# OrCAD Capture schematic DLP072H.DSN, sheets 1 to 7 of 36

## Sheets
1 PAGE35 - REVISION HISTORY
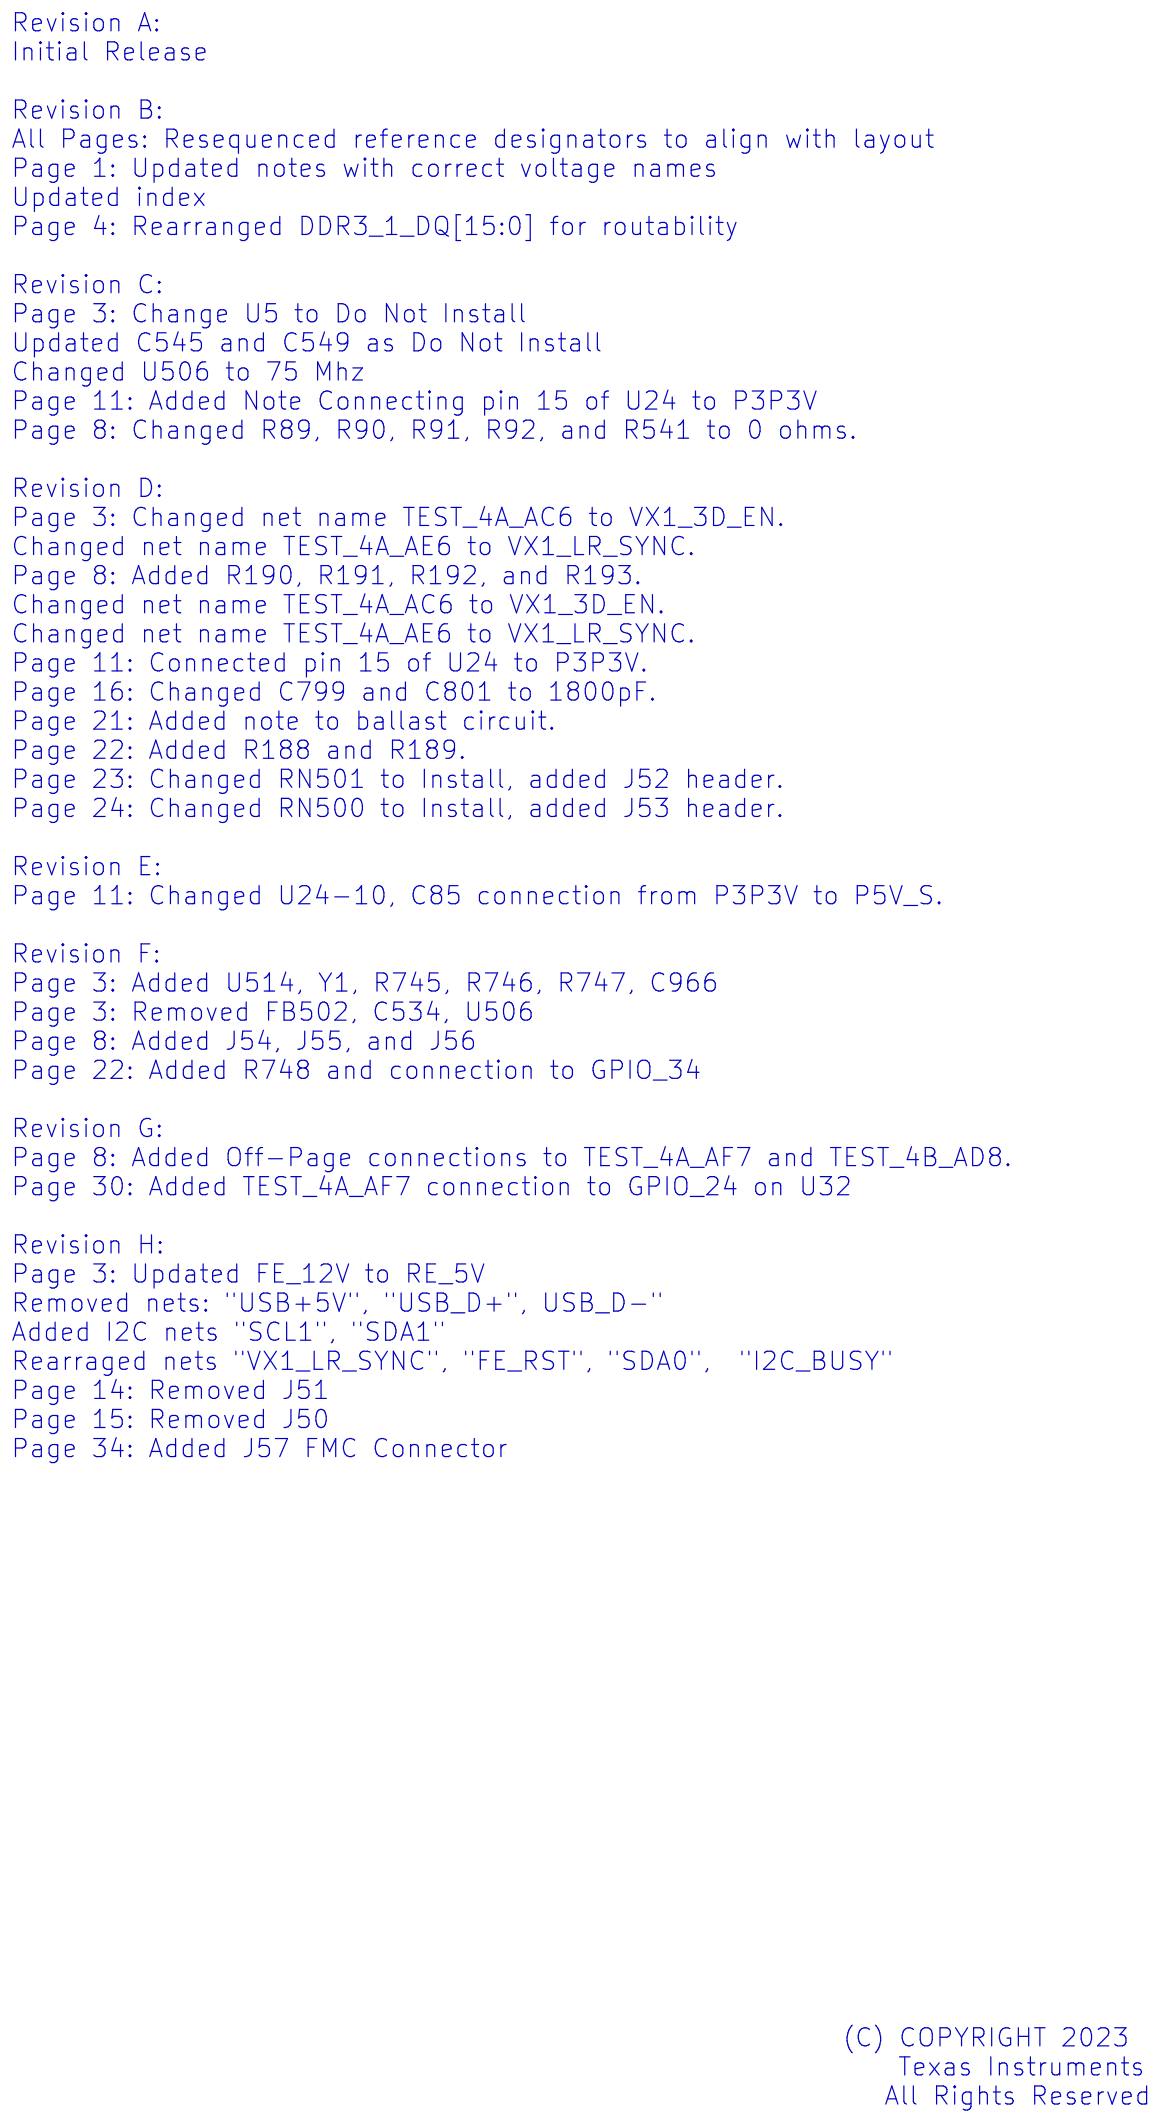
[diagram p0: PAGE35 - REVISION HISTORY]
2 PAGE34 - OUTPUT FMC CONNECTOR: size D
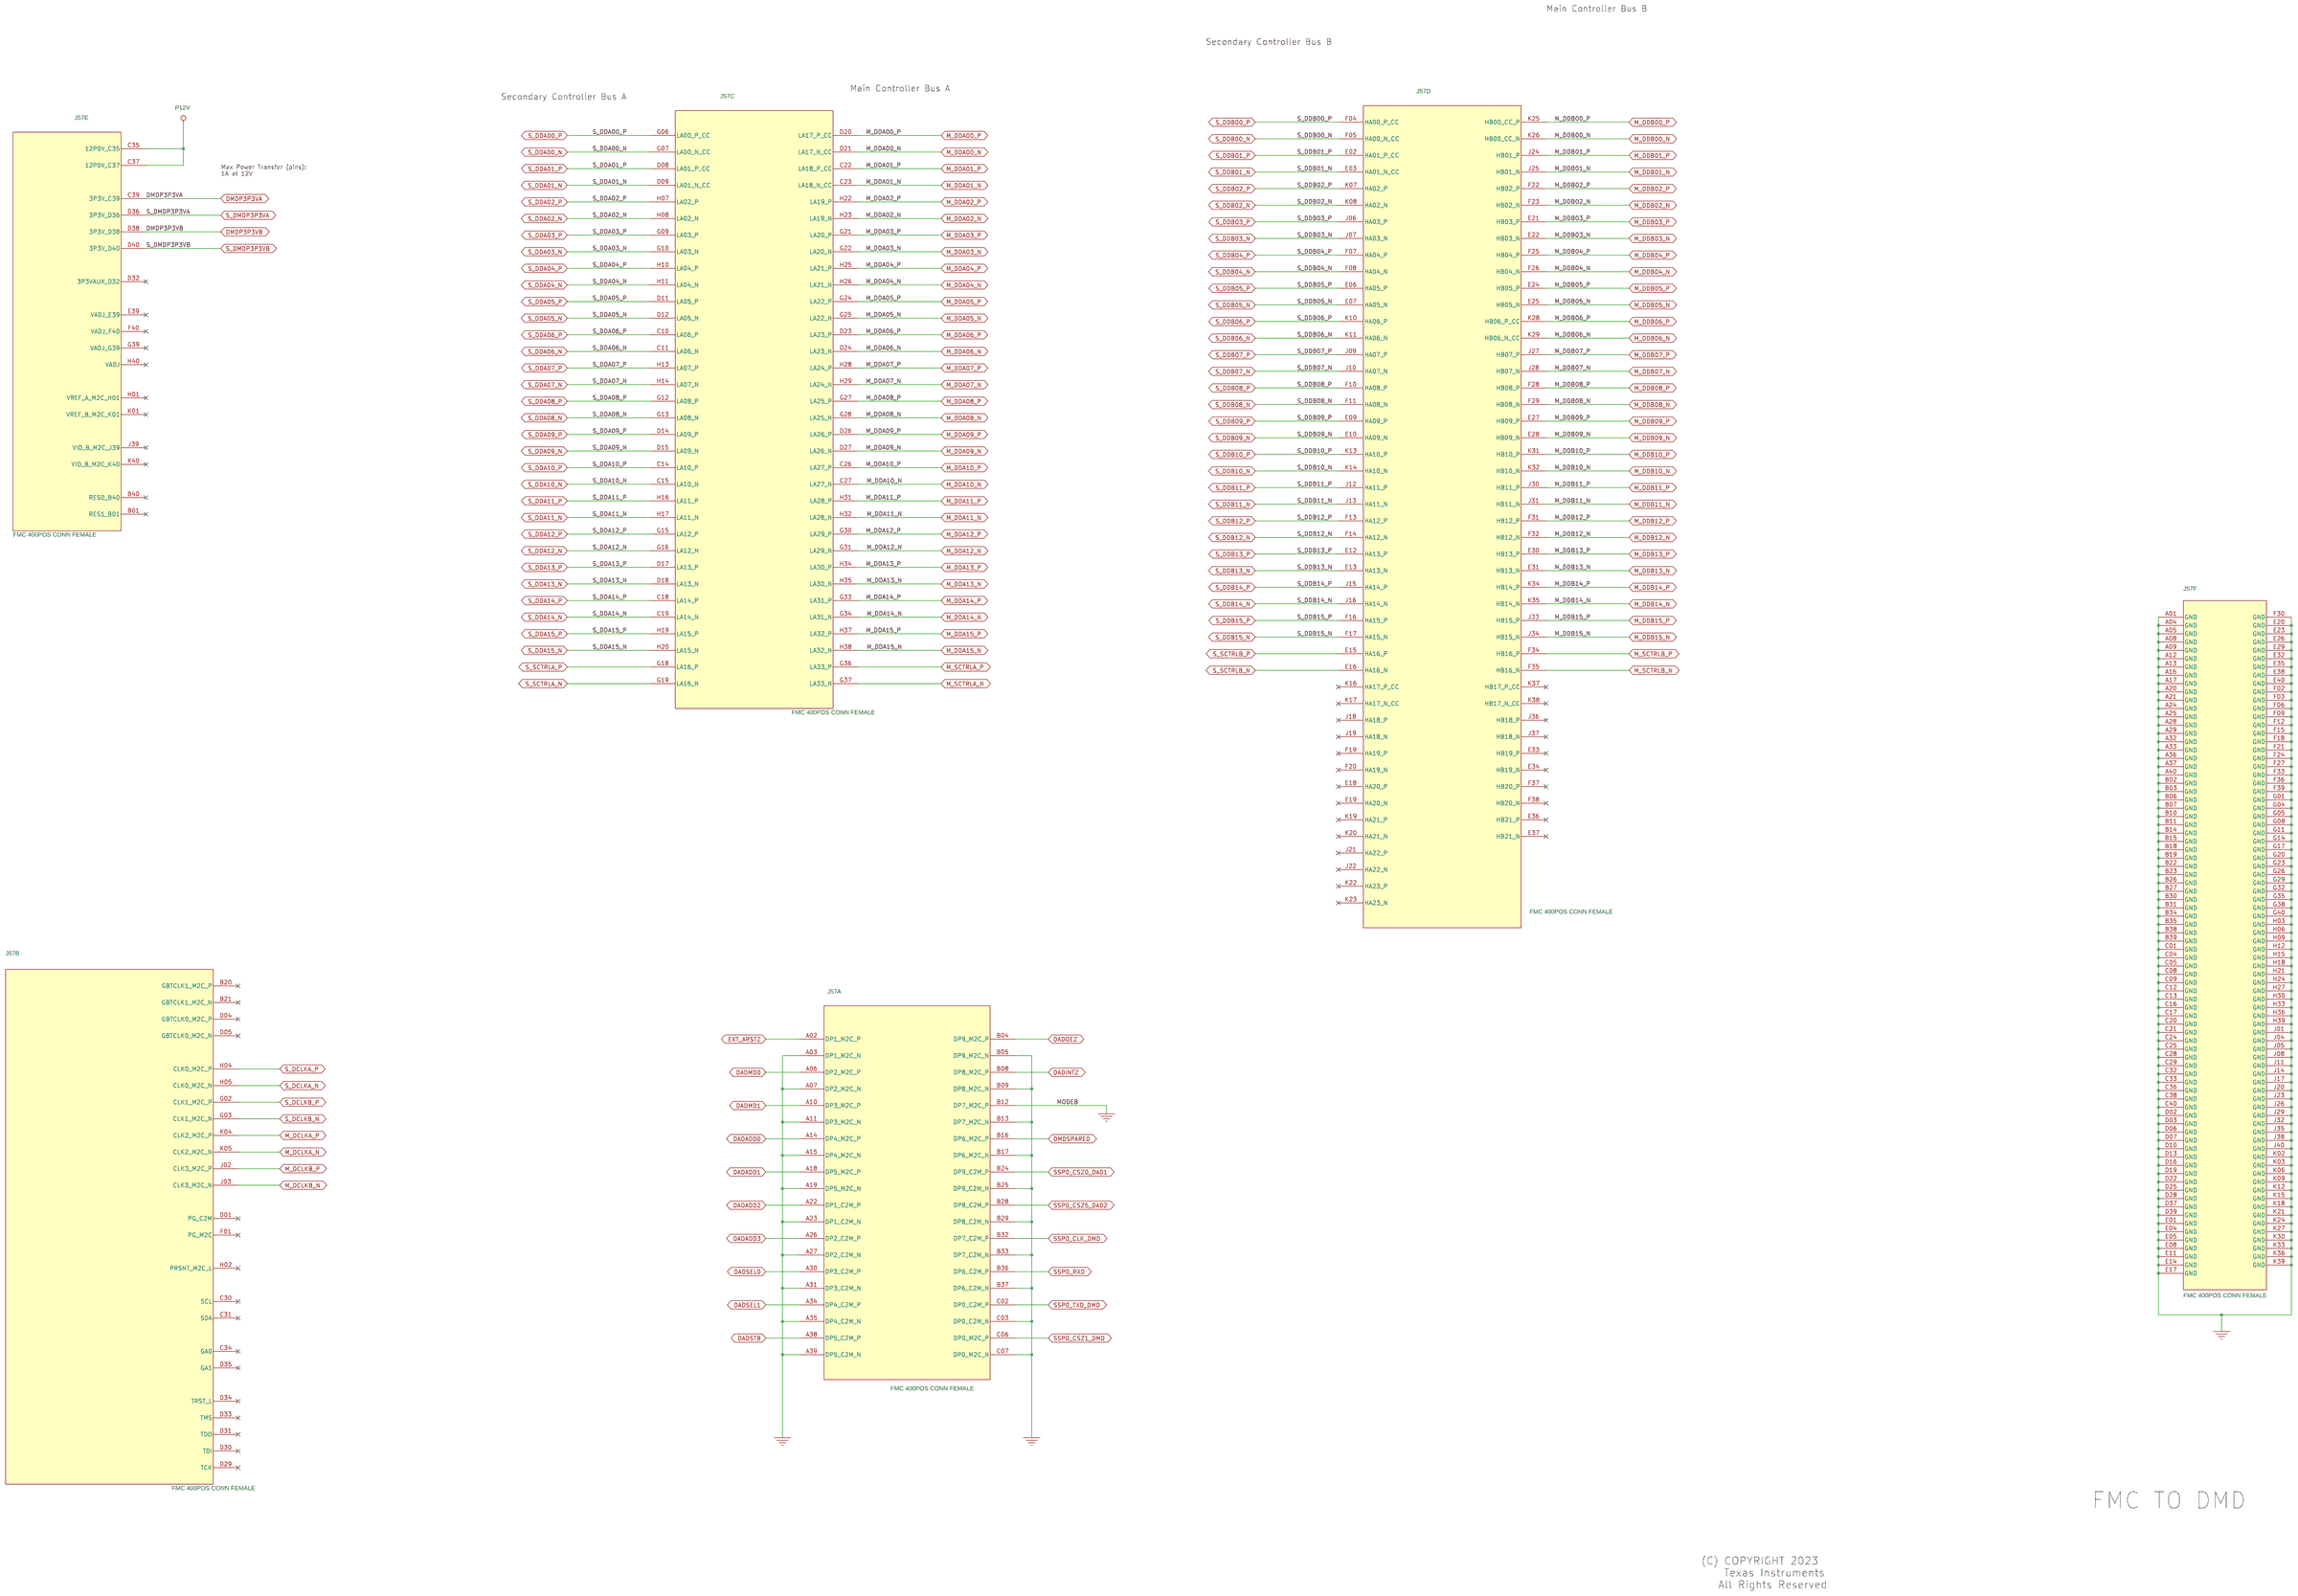
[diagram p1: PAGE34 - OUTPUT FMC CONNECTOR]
3 PAGE01 - TITLE
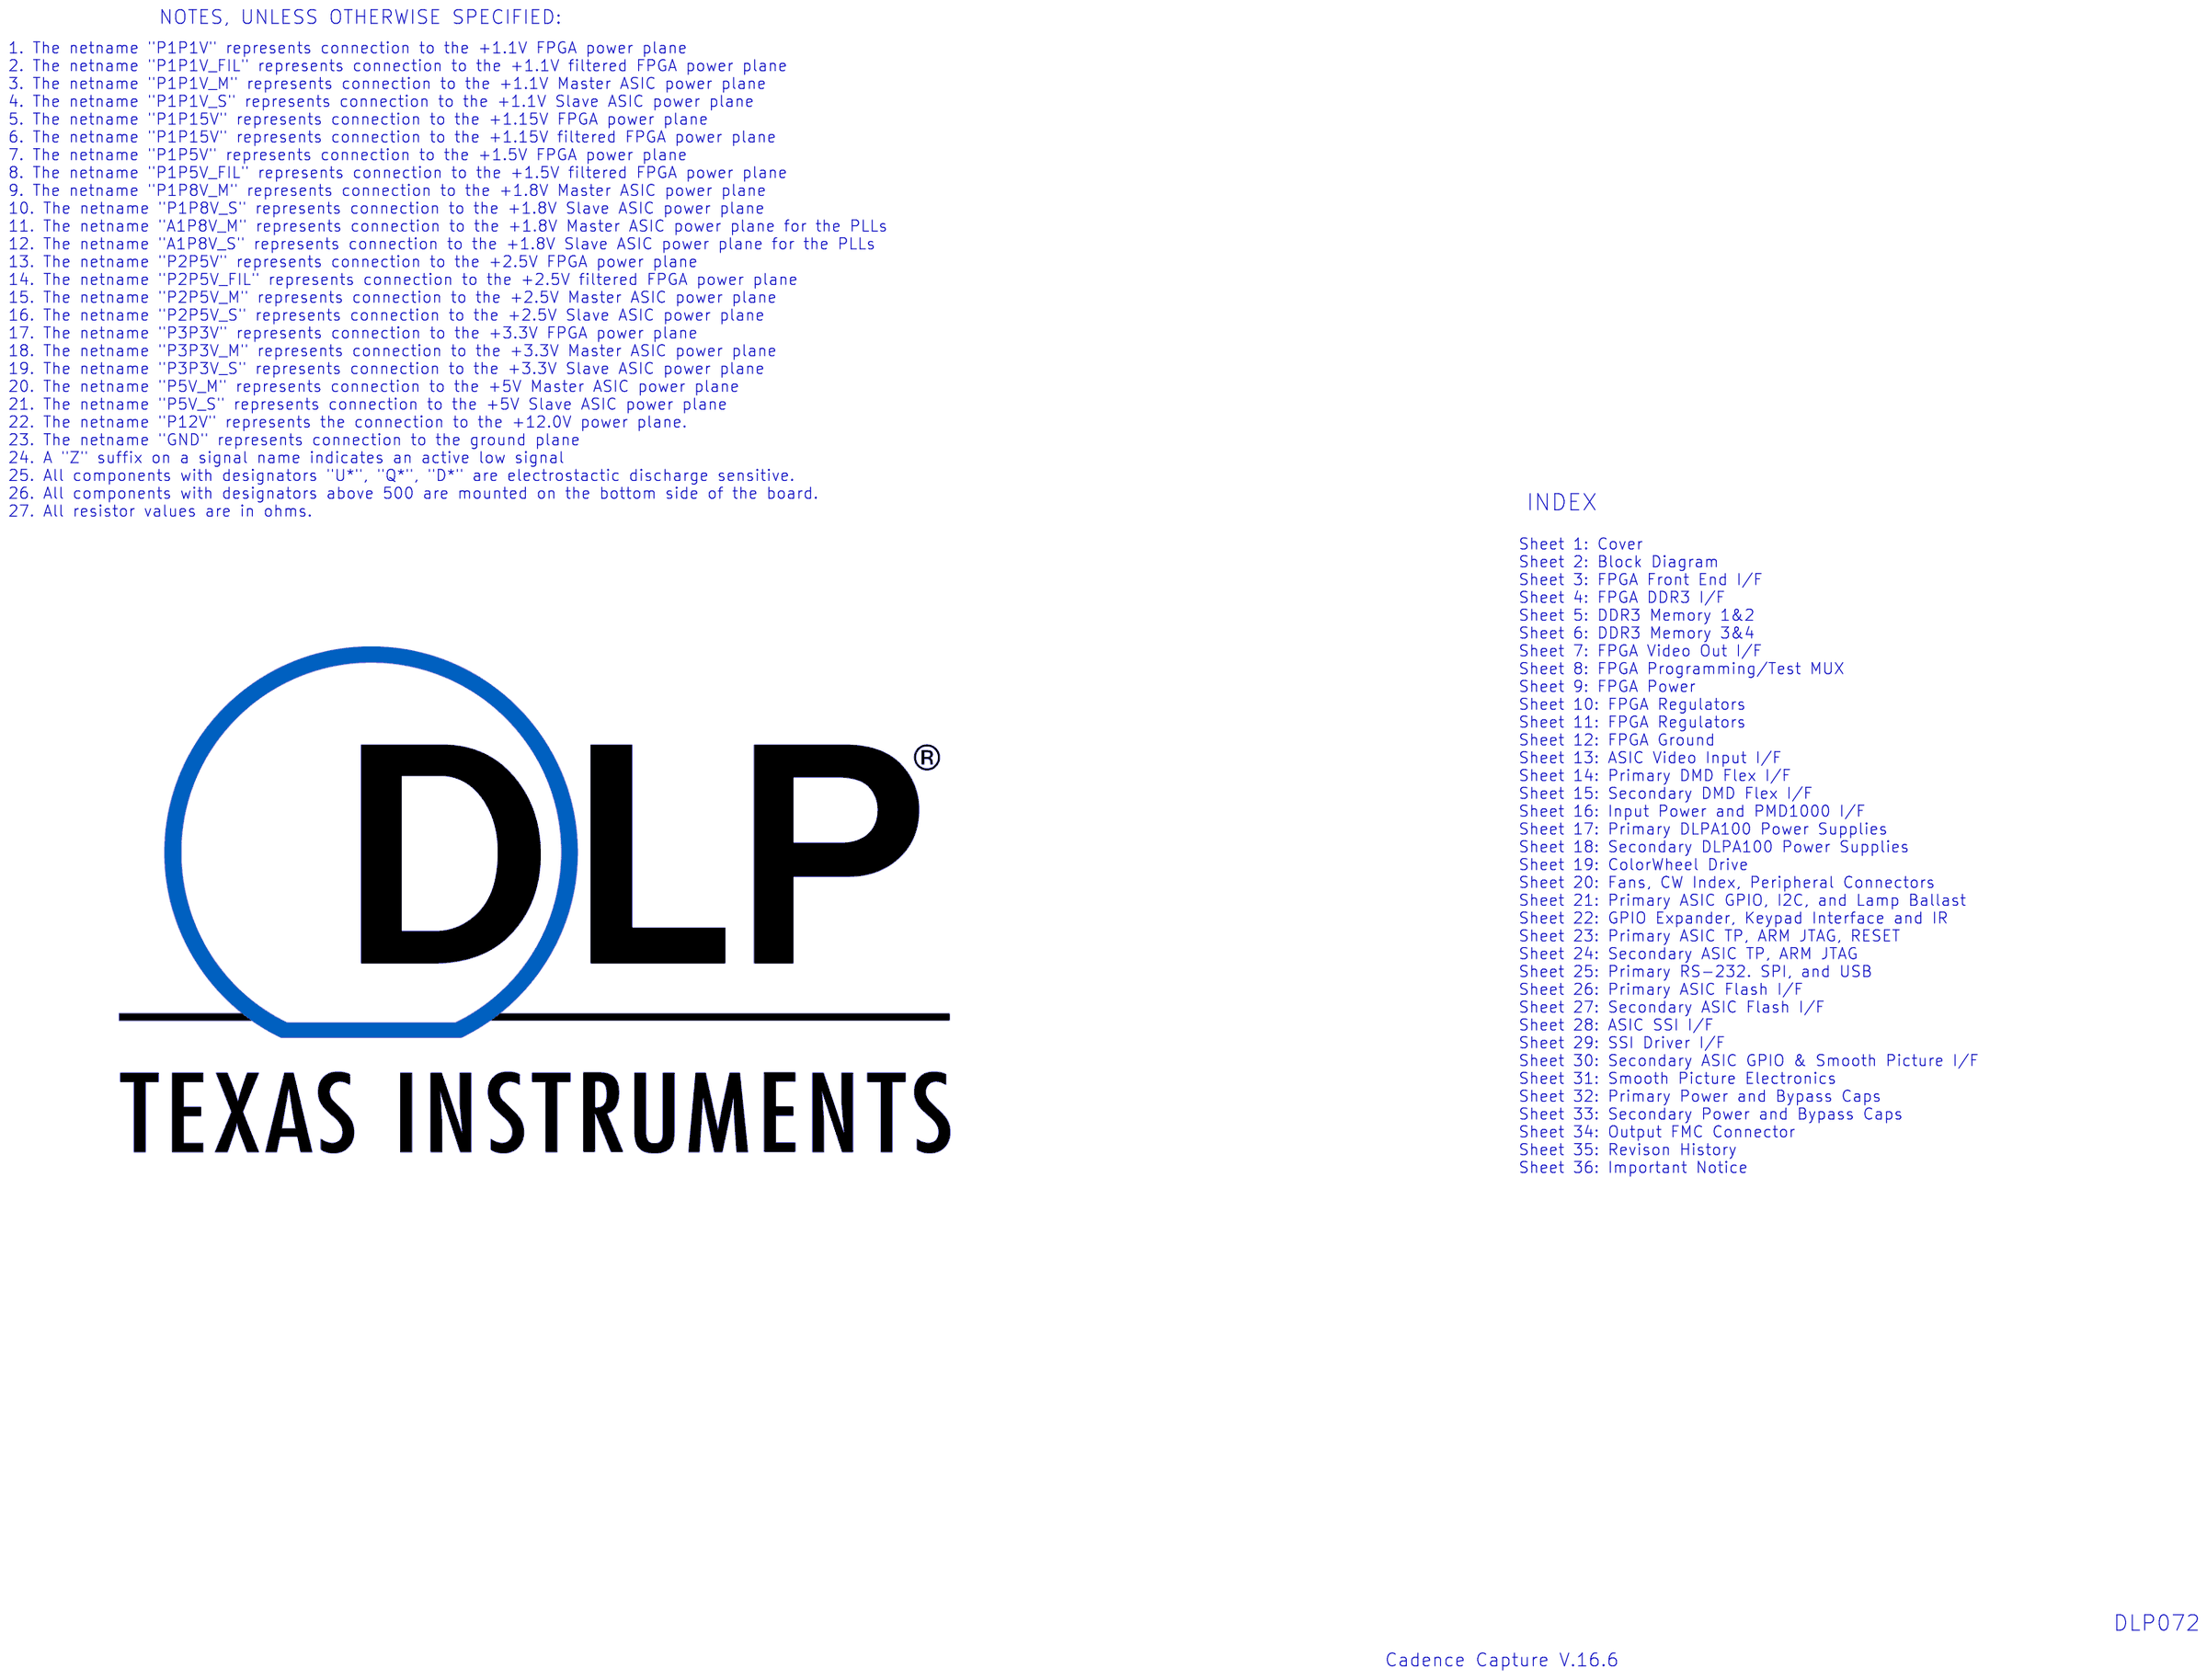
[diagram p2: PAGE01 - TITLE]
4 PAGE02 - BLOCK DIAGRAM
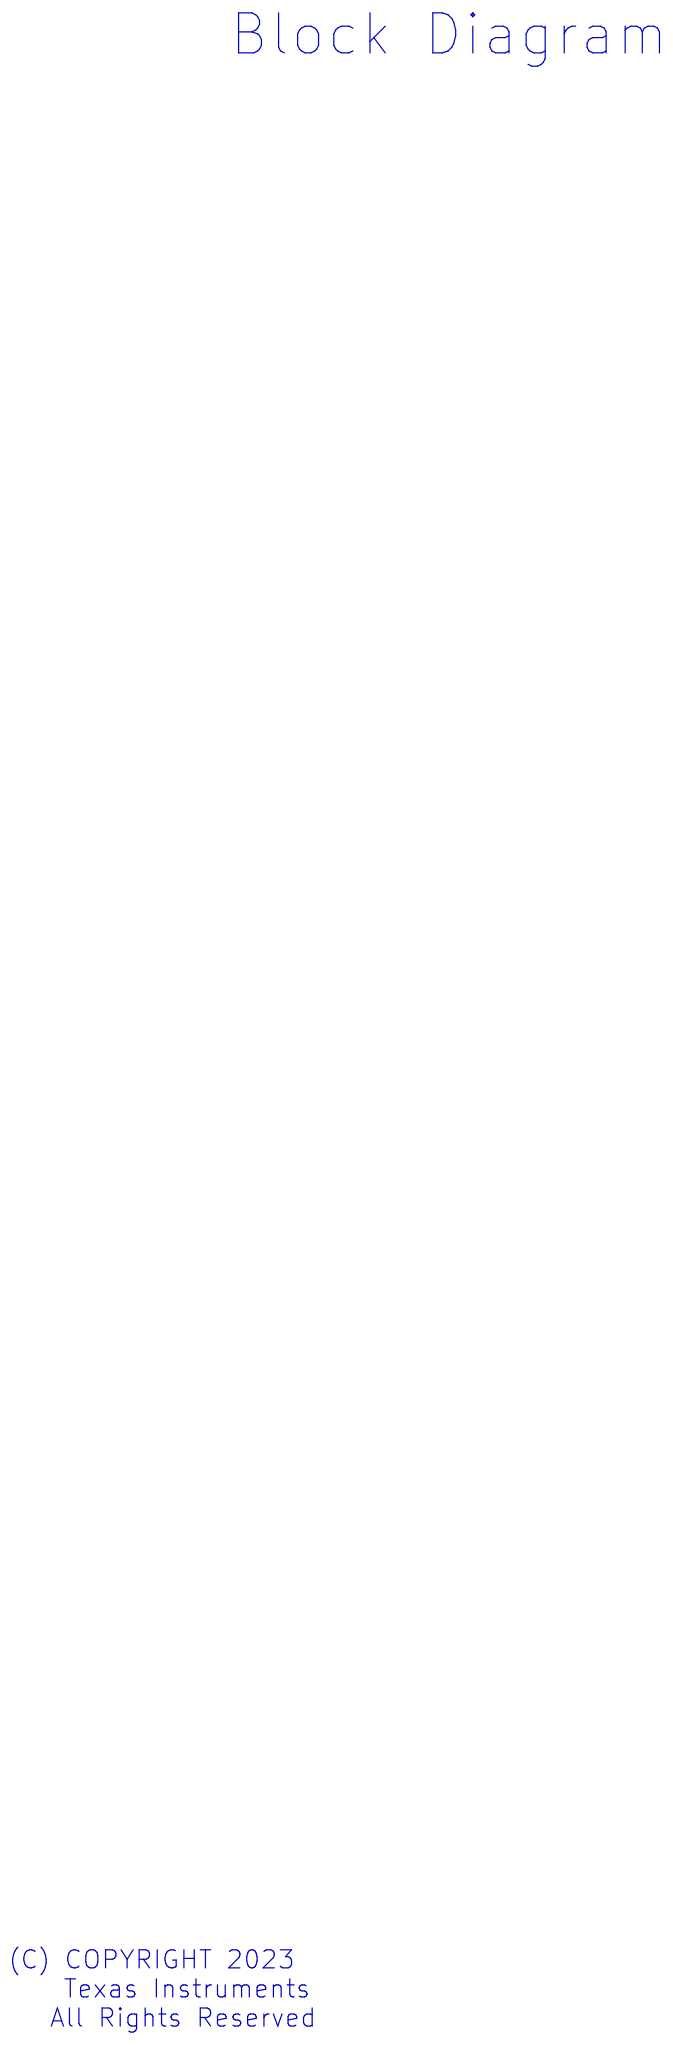
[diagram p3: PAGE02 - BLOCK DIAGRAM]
5 PAGE05 - DDR3 Memory: size A3
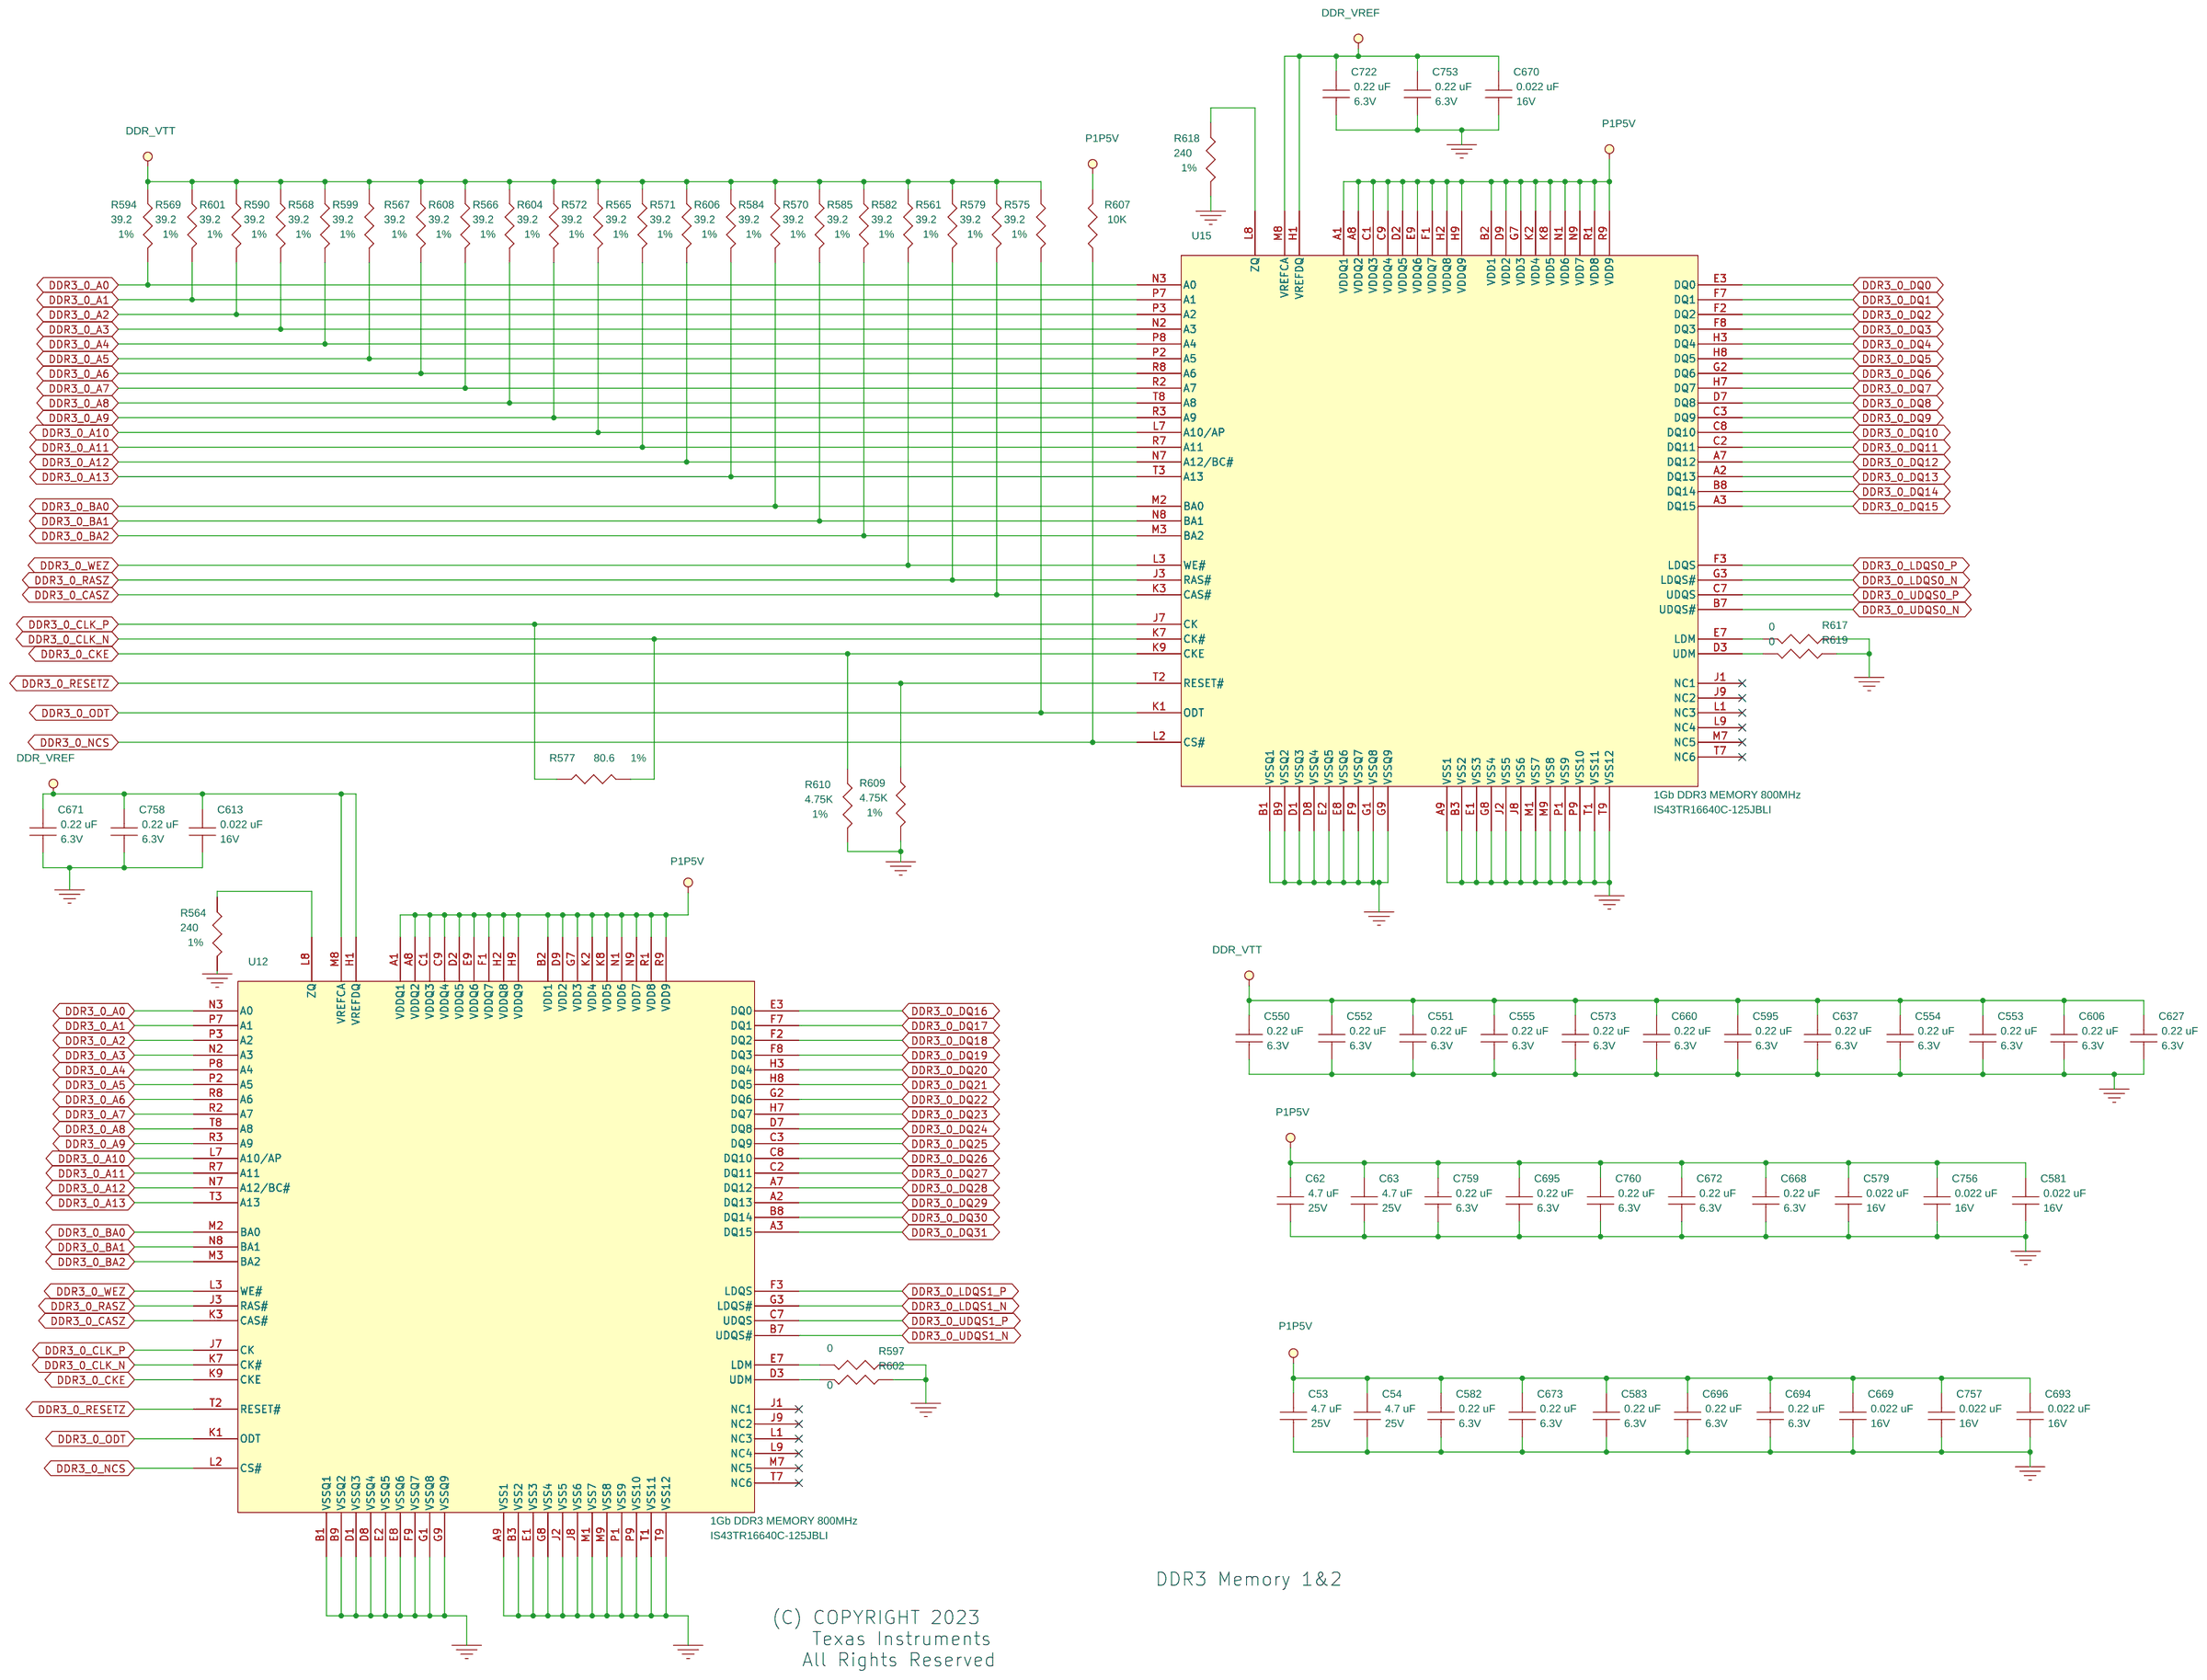
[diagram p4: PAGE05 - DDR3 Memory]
6 PAGE06 - DDR3 Memory: size A3
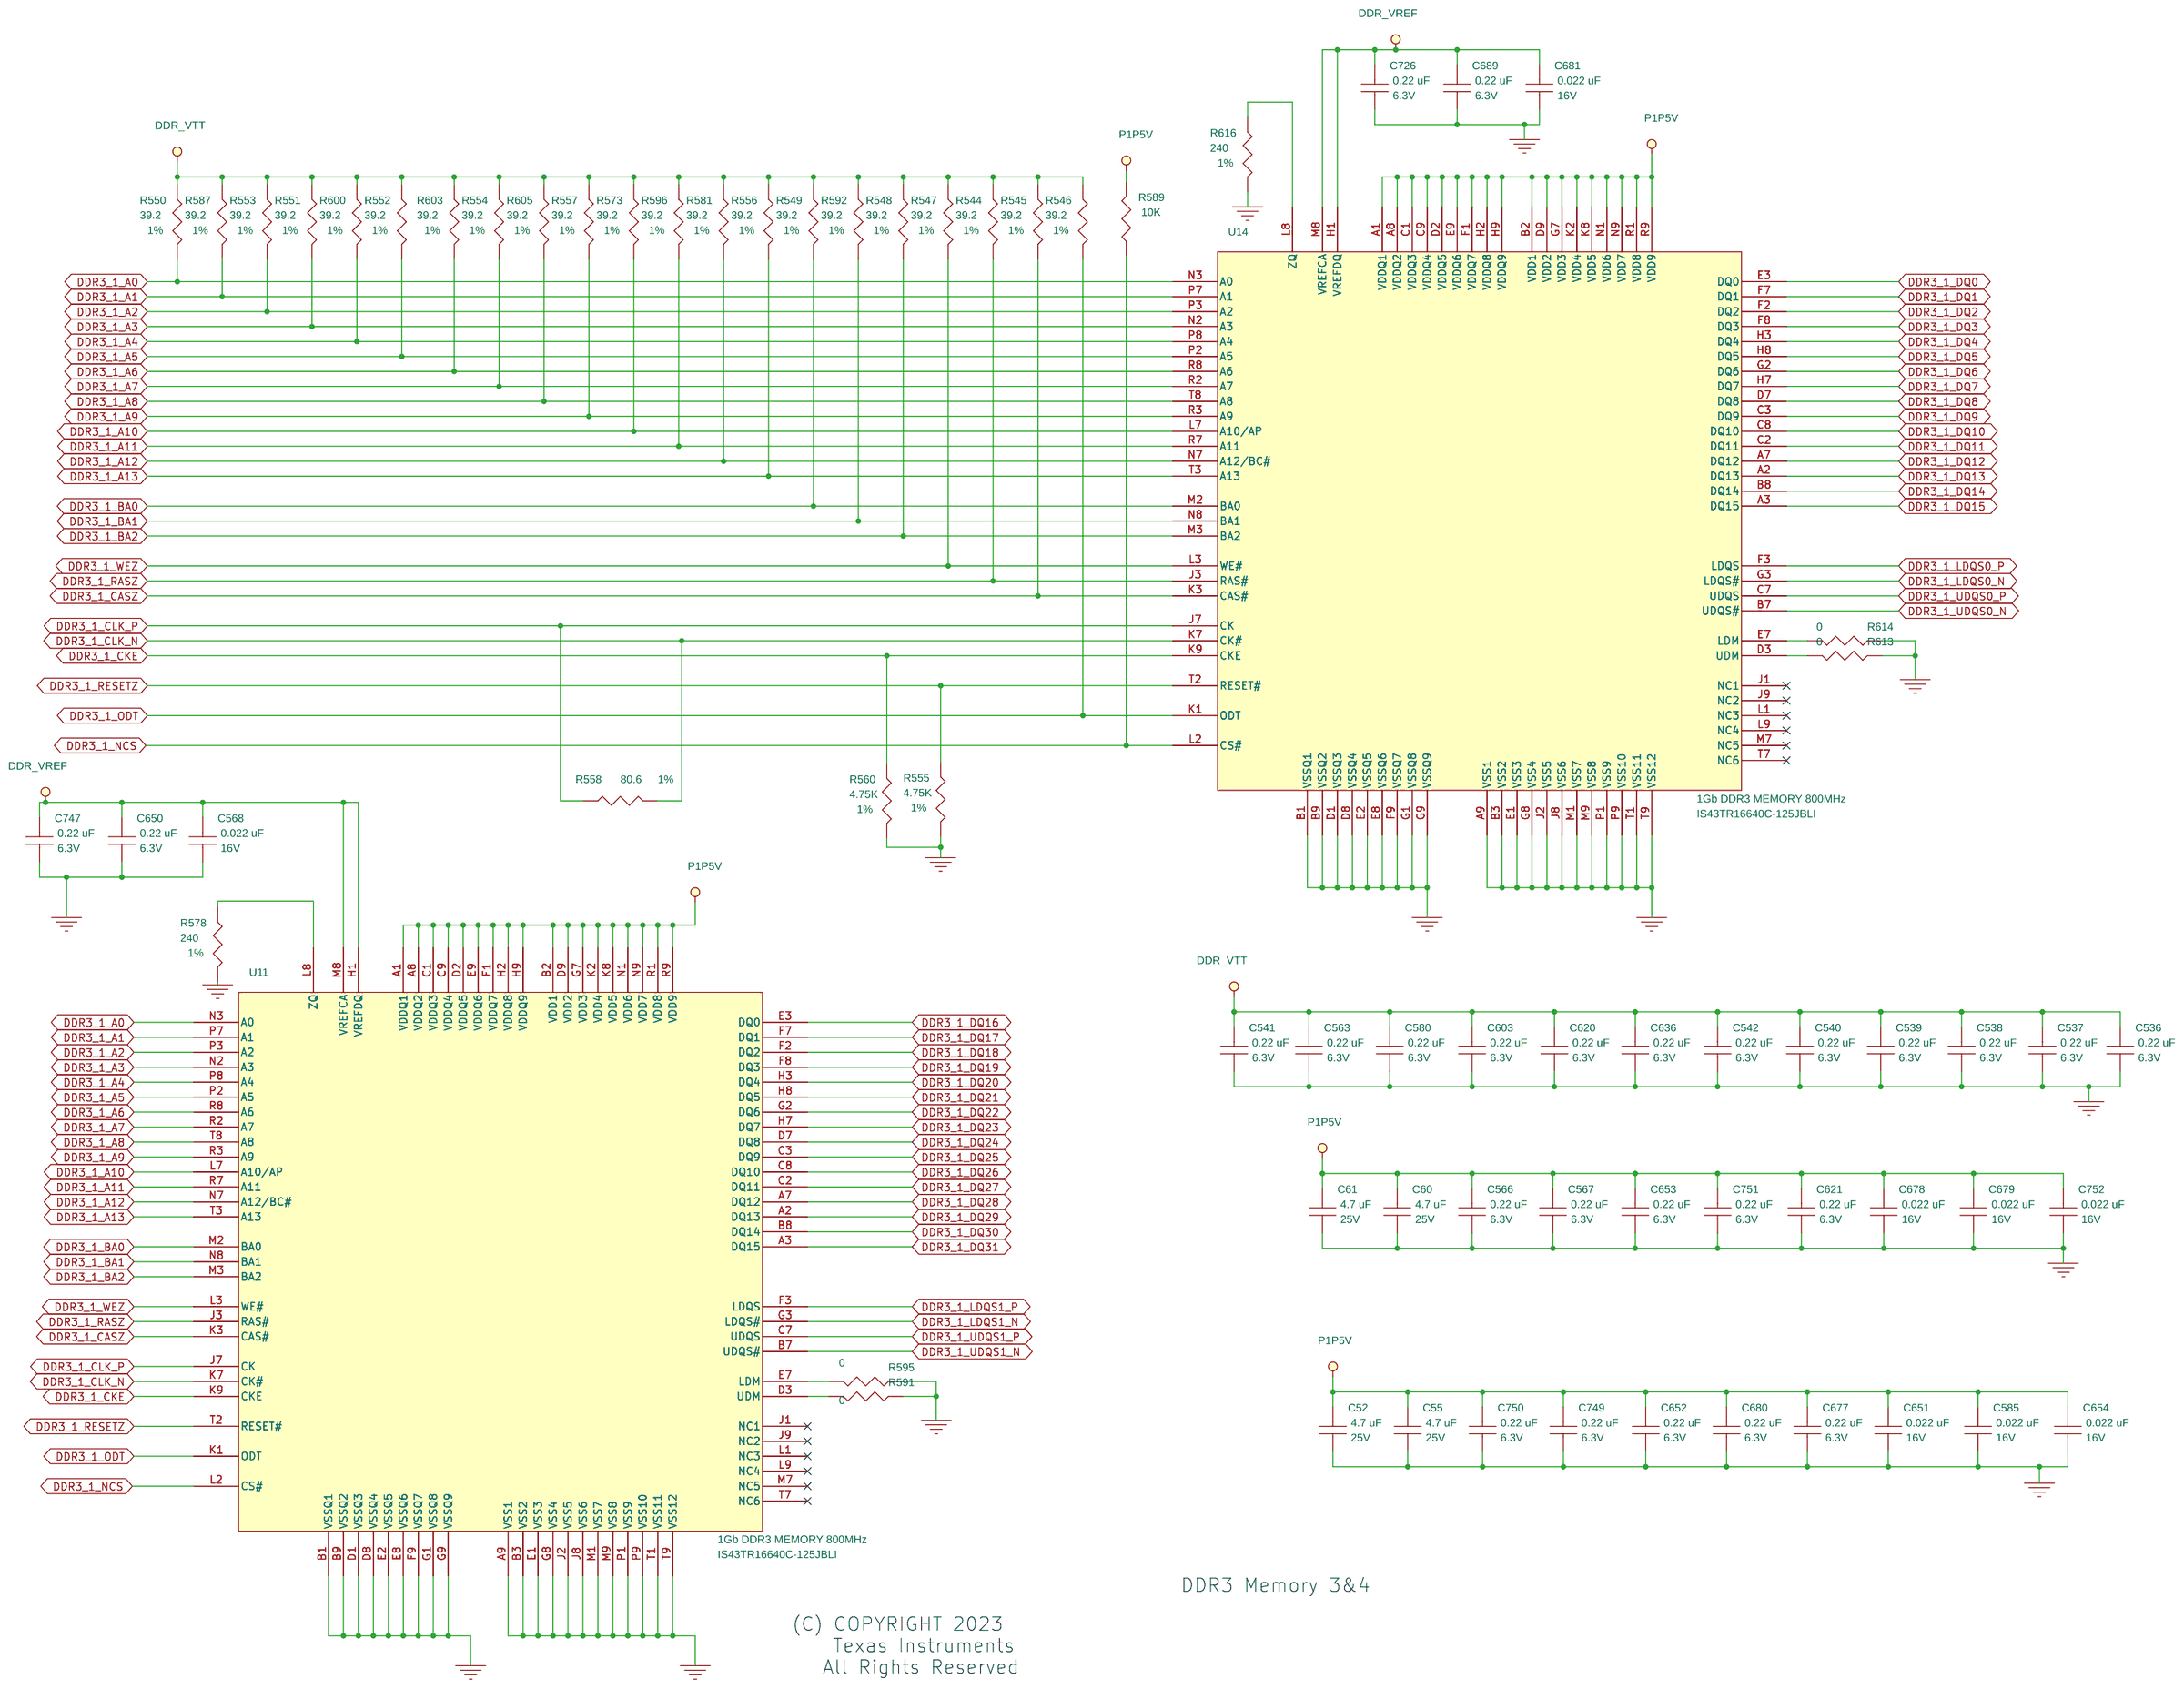
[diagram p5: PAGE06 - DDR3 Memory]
7 PAGE09 - FPGA POWER: size A3
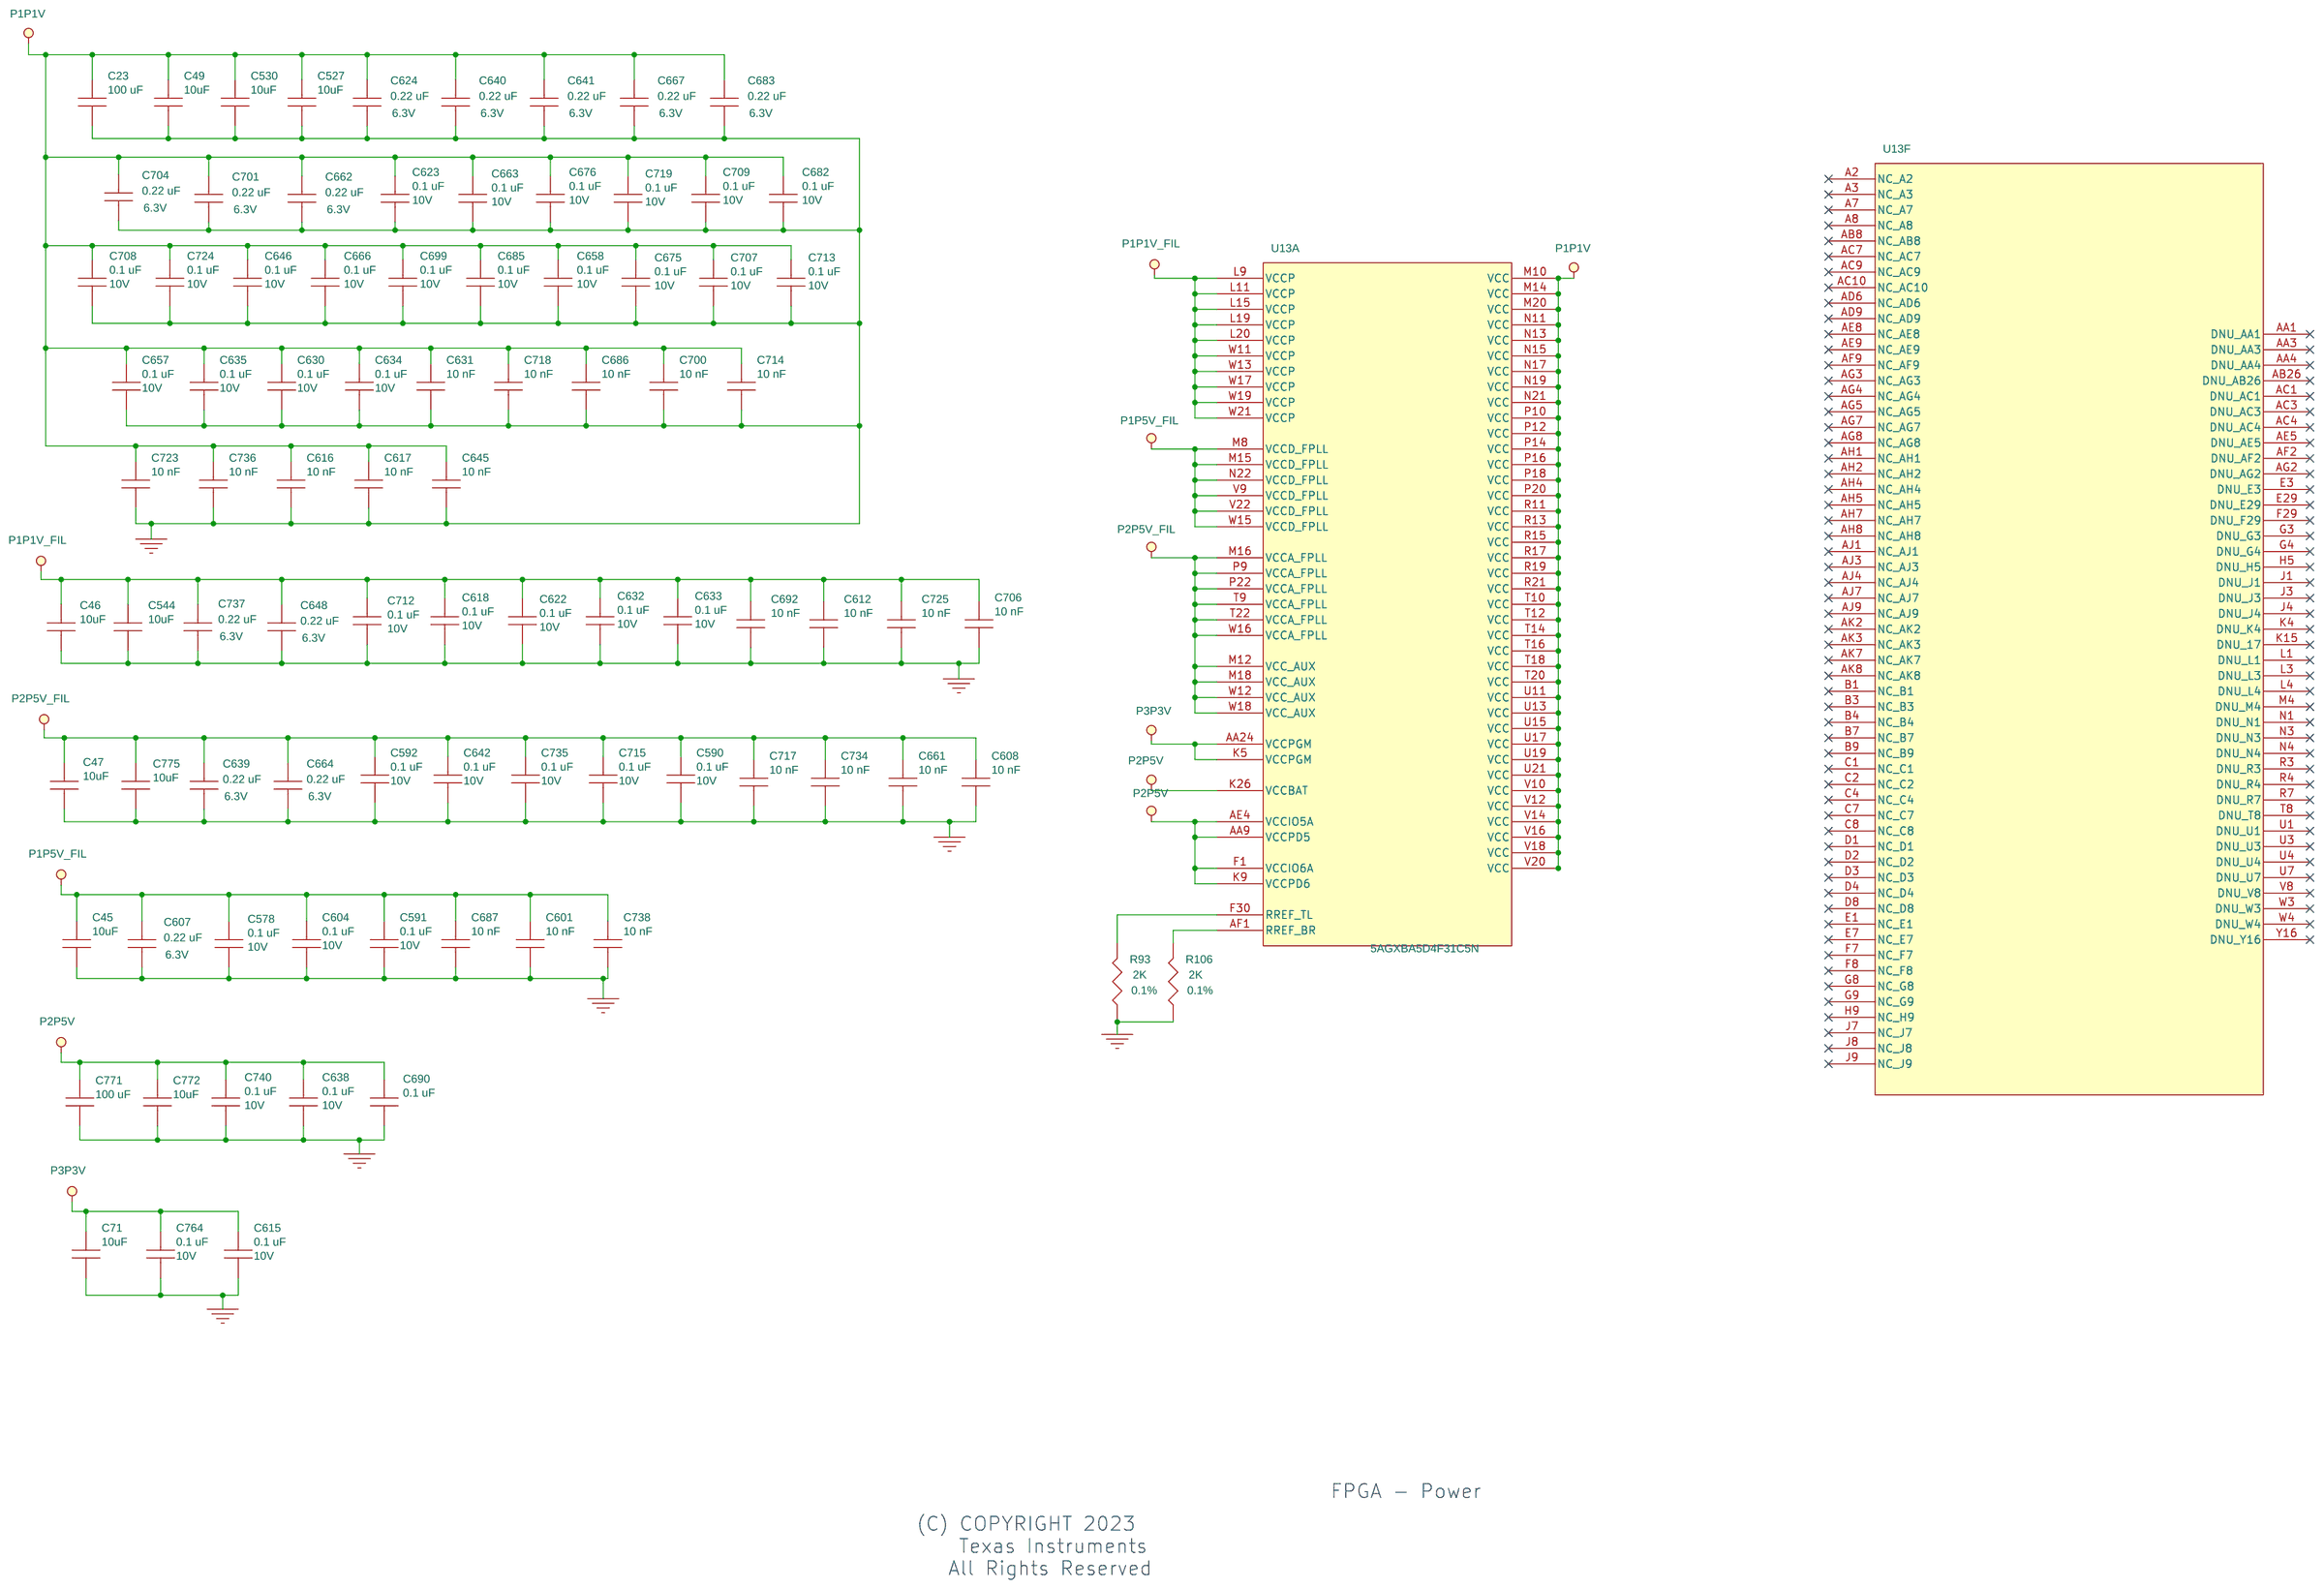
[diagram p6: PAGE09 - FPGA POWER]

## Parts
sheet PAGE05 - DDR3 Memory
C53  4.7 uF  [CAP_0805]
C54  4.7 uF  [CAP_0805]
C62  4.7 uF  [CAP_0805]
C63  4.7 uF  [CAP_0805]
C550  0.22 uF  [CAP_0402]
C551  0.22 uF  [CAP_0402]
C552  0.22 uF  [CAP_0402]
C553  0.22 uF  [CAP_0402]
C554  0.22 uF  [CAP_0402]
C555  0.22 uF  [CAP_0402]
C573  0.22 uF  [CAP_0402]
C579  0.022 uF  [CAP_0402]
C581  0.022 uF  [CAP_0402]
C582  0.22 uF  [CAP_0402]
C583  0.22 uF  [CAP_0402]
C595  0.22 uF  [CAP_0402]
C606  0.22 uF  [CAP_0402]
C613  0.022 uF  [CAP_0402]
C627  0.22 uF  [CAP_0402]
C637  0.22 uF  [CAP_0402]
C660  0.22 uF  [CAP_0402]
C668  0.22 uF  [CAP_0402]
C669  0.022 uF  [CAP_0402]
C670  0.022 uF  [CAP_0402]
C671  0.22 uF  [CAP_0402]
C672  0.22 uF  [CAP_0402]
C673  0.22 uF  [CAP_0402]
C693  0.022 uF  [CAP_0402]
C694  0.22 uF  [CAP_0402]
C695  0.22 uF  [CAP_0402]
C696  0.22 uF  [CAP_0402]
C722  0.22 uF  [CAP_0402]
C753  0.22 uF  [CAP_0402]
C756  0.022 uF  [CAP_0402]
C757  0.022 uF  [CAP_0402]
C758  0.22 uF  [CAP_0402]
C759  0.22 uF  [CAP_0402]
C760  0.22 uF  [CAP_0402]
R561  39.2  [RES_0402]
R564  240  [RES_0402]
R565  39.2  [RES_0402]
R566  39.2  [RES_0402]
R567  39.2  [RES_0402]
R568  39.2  [RES_0402]
R569  39.2  [RES_0402]
R570  39.2  [RES_0402]
R571  39.2  [RES_0402]
R572  39.2  [RES_0402]
R575  39.2  [RES_0402]
R577  80.6  [RES_0402]
R579  39.2  [RES_0402]
R582  39.2  [RES_0402]
R584  39.2  [RES_0402]
R585  39.2  [RES_0402]
R590  39.2  [RES_0402]
R594  39.2  [RES_0402]
R597  0  [RES_0402]
R599  39.2  [RES_0402]
R601  39.2  [RES_0402]
R602  0  [RES_0402]
R604  39.2  [RES_0402]
R606  39.2  [RES_0402]
R607  10K  [RES_0402]
R608  39.2  [RES_0402]
R609  4.75K  [RES_0402]
R610  4.75K  [RES_0402]
R617  0  [RES_0402]
R618  240  [RES_0402]
R619  0  [RES_0402]
U12  1Gb DDR3 MEMORY 800MHz  [BGA96-JT_MICRON]
U15  1Gb DDR3 MEMORY 800MHz  [BGA96-JT_MICRON]
sheet PAGE06 - DDR3 Memory
C52  4.7 uF  [CAP_0805]
C55  4.7 uF  [CAP_0805]
C60  4.7 uF  [CAP_0805]
C61  4.7 uF  [CAP_0805]
C536  0.22 uF  [CAP_0402]
C537  0.22 uF  [CAP_0402]
C538  0.22 uF  [CAP_0402]
C539  0.22 uF  [CAP_0402]
C540  0.22 uF  [CAP_0402]
C541  0.22 uF  [CAP_0402]
C542  0.22 uF  [CAP_0402]
C563  0.22 uF  [CAP_0402]
C566  0.22 uF  [CAP_0402]
C567  0.22 uF  [CAP_0402]
C568  0.022 uF  [CAP_0402]
C580  0.22 uF  [CAP_0402]
C585  0.022 uF  [CAP_0402]
C603  0.22 uF  [CAP_0402]
C620  0.22 uF  [CAP_0402]
C621  0.22 uF  [CAP_0402]
C636  0.22 uF  [CAP_0402]
C650  0.22 uF  [CAP_0402]
C651  0.022 uF  [CAP_0402]
C652  0.22 uF  [CAP_0402]
C653  0.22 uF  [CAP_0402]
C654  0.022 uF  [CAP_0402]
C677  0.22 uF  [CAP_0402]
C678  0.022 uF  [CAP_0402]
C679  0.022 uF  [CAP_0402]
C680  0.22 uF  [CAP_0402]
C681  0.022 uF  [CAP_0402]
C689  0.22 uF  [CAP_0402]
C726  0.22 uF  [CAP_0402]
C747  0.22 uF  [CAP_0402]
C749  0.22 uF  [CAP_0402]
C750  0.22 uF  [CAP_0402]
C751  0.22 uF  [CAP_0402]
C752  0.022 uF  [CAP_0402]
R544  39.2  [RES_0402]
R545  39.2  [RES_0402]
R546  39.2  [RES_0402]
R547  39.2  [RES_0402]
R548  39.2  [RES_0402]
R549  39.2  [RES_0402]
R550  39.2  [RES_0402]
R551  39.2  [RES_0402]
R552  39.2  [RES_0402]
R553  39.2  [RES_0402]
R554  39.2  [RES_0402]
R555  4.75K  [RES_0402]
R556  39.2  [RES_0402]
R557  39.2  [RES_0402]
R558  80.6  [RES_0402]
R560  4.75K  [RES_0402]
R573  39.2  [RES_0402]
R578  240  [RES_0402]
R581  39.2  [RES_0402]
R587  39.2  [RES_0402]
R589  10K  [RES_0402]
R591  0  [RES_0402]
R592  39.2  [RES_0402]
R595  0  [RES_0402]
R596  39.2  [RES_0402]
R600  39.2  [RES_0402]
R603  39.2  [RES_0402]
R605  39.2  [RES_0402]
R613  0  [RES_0402]
R614  0  [RES_0402]
R616  240  [RES_0402]
U11  1Gb DDR3 MEMORY 800MHz  [BGA96-JT_MICRON]
U14  1Gb DDR3 MEMORY 800MHz  [BGA96-JT_MICRON]
sheet PAGE09 - FPGA POWER
C23  100 uF  [CAP_1206]
C45  10uF  [CAP_0402]
C46  10uF  [CAP_0402]
C47  10uF  [CAP_0402]
C49  10uF  [CAP_0402]
C71  10uF  [CAP_0402]
C527  10uF  [CAP_0402]
C530  10uF  [CAP_0402]
C544  10uF  [CAP_0402]
C578  0.1 uF  [CAP_0402]
C590  0.1 uF  [CAP_0402]
C591  0.1 uF  [CAP_0402]
C592  0.1 uF  [CAP_0402]
C601  10 nF  [CAP_0402]
C604  0.1 uF  [CAP_0402]
C607  0.22 uF  [CAP_0402]
C608  10 nF  [CAP_0402]
C612  10 nF  [CAP_0402]
C615  0.1 uF  [CAP_0402]
C616  10 nF  [CAP_0402]
C617  10 nF  [CAP_0402]
C618  0.1 uF  [CAP_0402]
C622  0.1 uF  [CAP_0402]
C623  0.1 uF  [CAP_0402]
C624  0.22 uF  [CAP_0402]
C630  0.1 uF  [CAP_0402]
C631  10 nF  [CAP_0402]
C632  0.1 uF  [CAP_0402]
C633  0.1 uF  [CAP_0402]
C634  0.1 uF  [CAP_0402]
C635  0.1 uF  [CAP_0402]
C638  0.1 uF  [CAP_0402]
C639  0.22 uF  [CAP_0402]
C640  0.22 uF  [CAP_0402]
C641  0.22 uF  [CAP_0402]
C642  0.1 uF  [CAP_0402]
C645  10 nF  [CAP_0402]
C646  0.1 uF  [CAP_0402]
C648  0.22 uF  [CAP_0402]
C657  0.1 uF  [CAP_0402]
C658  0.1 uF  [CAP_0402]
C661  10 nF  [CAP_0402]
C662  0.22 uF  [CAP_0402]
C663  0.1 uF  [CAP_0402]
C664  0.22 uF  [CAP_0402]
C666  0.1 uF  [CAP_0402]
C667  0.22 uF  [CAP_0402]
C675  0.1 uF  [CAP_0402]
C676  0.1 uF  [CAP_0402]
C682  0.1 uF  [CAP_0402]
C683  0.22 uF  [CAP_0402]
C685  0.1 uF  [CAP_0402]
C686  10 nF  [CAP_0402]
C687  10 nF  [CAP_0402]
C690  0.1 uF  [CAP_0402]
C692  10 nF  [CAP_0402]
C699  0.1 uF  [CAP_0402]
C700  10 nF  [CAP_0402]
C701  0.22 uF  [CAP_0402]
C704  0.22 uF  [CAP_0402]
C706  10 nF  [CAP_0402]
C707  0.1 uF  [CAP_0402]
C708  0.1 uF  [CAP_0402]
C709  0.1 uF  [CAP_0402]
C712  0.1 uF  [CAP_0402]
C713  0.1 uF  [CAP_0402]
C714  10 nF  [CAP_0402]
C715  0.1 uF  [CAP_0402]
C717  10 nF  [CAP_0402]
C718  10 nF  [CAP_0402]
C719  0.1 uF  [CAP_0402]
C723  10 nF  [CAP_0402]
C724  0.1 uF  [CAP_0402]
C725  10 nF  [CAP_0402]
C734  10 nF  [CAP_0402]
C735  0.1 uF  [CAP_0402]
C736  10 nF  [CAP_0402]
C737  0.22 uF  [CAP_0402]
C738  10 nF  [CAP_0402]
C740  0.1 uF  [CAP_0402]
C764  0.1 uF  [CAP_0402]
C771  100 uF  [CAP_1206]
C772  10uF  [CAP_0402]
C775  10uF  [CAP_0402]
R93  2K  [RES_0402]
R106  2K  [RES_0402]
U13  5AGXBA5D4F31C5N  [FBGA-896]  (sections A,B,C,D,E,F,G,H,I)
sheet PAGE34 - OUTPUT FMC CONNECTOR
J57  FMC 400POS CONN FEMALE  [CONN400-ASP-134486-01_SAM_MOD]  (sections A,B,C,D,E,F)

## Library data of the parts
C52-C55 C60-C63 = CAP_NP: Capacitor; CCA: 42; MFG: TDK; Part Number: C2012X7R1E475K125AB; RATING: 25V; TOLERANCE: 10%; Type: X7R
C536-C542 C550-C555 C563 C566 C567 C573 C580 C582 C583 C595 C603 C606 C620 C621 C627 C636 C637 C650 C652 C653 C660 C668 C671-C673 C677 C680 C689 C694-C696 C722 C726 C747 C749-C751 C753 C758-C760 = CAP_NP: Capacitor; ALT_SYMBOLS: 0402-1MM; CCA: 39; MFG: SAMSUNG; Part Number: CL05A224KQ5NNNC; RATING: 6.3V; TOLERANCE: 10%; Type: X5R
C568 C579 C581 C585 C613 C651 C654 C669 C670 C678 C679 C681 C693 C752 C756 C757 = CAP_NP: Capacitor; ALT_SYMBOLS: 0402-1MM; CCA: 5; MFG: AVX; Part Number: 0402YC223KAT2A; RATING: 16V; TOLERANCE: 10%; Type: X7R
R544-R554 R556 R557 R561 R565-R573 R575 R579 R581 R582 R584 R585 R587 R590 R592 R594 R596 R599-R601 R603-R606 R608 = R: Resistor; ALT_SYMBOLS: 0402-1MM; CCA: 70; ICA_MFR_NAME: PANASONIC; ICA_PARTNUM: $$1785048$$ERJ-3GSYJ102; MFG: PANASONIC; Part Number: ERJ-2RKF39R2X; RATING: 1/10W; TOLERANCE: 1%
R564 R578 R616 R618 = R: Resistor; ALT_SYMBOLS: 0402-1MM; CCA: 73; ICA_MFR_NAME: PANASONIC; ICA_PARTNUM: $$1785048$$ERJ-3GSYJ102; MFG: PANASONIC; Part Number: ERJ-2RKF2400X; RATING: 1/10W; TOLERANCE: 1%
R558 R577 = R: Resistor; ALT_SYMBOLS: 0402-1MM; CCA: 71; ICA_MFR_NAME: PANASONIC; ICA_PARTNUM: $$1785048$$ERJ-3GSYJ102; MFG: PANASONIC; Part Number: ERJ-2RKF80R6X; RATING: 1/10W; TOLERANCE: 1%
R591 R595 R597 R602 R613 R614 R617 R619 = R: Resistor; CCA: 62; ICA_MFR_NAME: PANASONIC; ICA_PARTNUM: $$1785048$$ERJ-3GSYJ102; MFG: PANASONIC; Part Number: ERJ-2GE0R00X; RATING: 1/10W; SOURCE: DIGI P0.0JCT-ND
R589 R607 = R: Resistor; CCA: 65; ICA_MFR_NAME: PANASONIC; ICA_PARTNUM: $$1785048$$ERJ-3GSYJ102; MFG: PANASONIC; Part Number: ERJ-2GEJ103X; RATING: 1/10W; SOURCE: DIGI P10.0KLCT-ND; TOLERANCE: 5%
R555 R560 R609 R610 = R: Resistor; ALT_SYMBOLS: 0402-1MM; CCA: 53; ICA_MFR_NAME: PANASONIC; ICA_PARTNUM: $$1785048$$ERJ-3GSYJ102; MFG: VISHAY/DALE; Part Number: ERJ-2RKF4751X; RATING: 1/10W; TOLERANCE: 1%
U11 U12 U14 U15 = MT41J128M16_0: IC, Memory; CCA: 135; MFG: ISSI; Part Number: IS43TR16640C-125JBLI; RATING: 1.35 V
C23 C771 = CER_100UF_6.3V_20%_X5R_1206: CCA: 114; MFG: KEMET; Part Number: C1206C107M9PACTU; Type: X5R
C45-C47 C49 C71 C527 C530 C544 C772 C775 = CER_10UF_6.3V_20%_X5R_0402: Part Number: CL05A106MQ5NUNC
C578 C590-C592 C604 C615 C618 C622 C623 C630 C632-C635 C638 C642 C646 C657 C658 C663 C666 C675 C676 C682 C685 C690 C699 C707-C709 C712 C713 C715 C719 C724 C735 C740 C764 = CER_0.1UF_16V_10%_X5R_0402: CCA: 34; MFG: KEMET; Part Number: C0402C104K8RACTU; Rating: 10V; SOURCE: DIGI 399-3520-1-ND; Type: X7R
C601 C608 C612 C616 C617 C631 C645 C661 C686 C687 C692 C700 C706 C714 C717 C718 C723 C725 C734 C736 C738 = CER_10_nF_25V_10%_X5R_0402: Part Number: C1005X7R1H103K050BB
C607 C624 C639-C641 C648 C662 C664 C667 C683 C701 C704 C737 = CAP_NP: Capacitor; CCA: 39; MFG: SAMSUNG; Part Number: CL05A224KQ5NNNC; RATING: 6.3V; SOURCE: DIGI 399-3491-1-ND; TOLERANCE: 10%; Type: X5R
R93 R106 = R: Resistor; CCA: 59; ICA_MFR_NAME: PANASONIC; ICA_PARTNUM: $$1785048$$ERJ-3GSYJ102; MFG: PANASONIC; Part Number: ERA-2AEB202X; RATING: 1/16W; SOURCE: DIGI P2.0KDCCT-ND; TOLERANCE: 0.1%
U13 = 5AGXMA5GF31: IC, FPGA; MFG: ALTERA
J57 = FMC_400POS_CONNECTOR: MFG: Samtec; PART NUMBER: ASP-134486-01

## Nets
GND: C23.2 C45.2 C46.2 C47.2 C49.2 C52.1 C53.1 C54.1 C55.1 C60.1 C61.1 C62.1 C63.1 C71.2 C527.2 C530.2 C536.1 C537.1 C538.1 C539.1 C540.1 C541.1 C542.1 C544.2 C550.1 C551.1 C552.1 C553.1 C554.1 C555.1 C563.1 C566.1 C567.1 C568.1 C573.1 C578.2 C579.1 C580.1 C581.1 C582.1 C583.1 C585.1 C590.2 C591.2 C592.2 C595.1 C601.2 C603.1 C604.2 C606.1 C607.2 C608.2 C612.2 C613.1 C615.2 C616.2 C617.2 C618.2 C620.1 C621.1 C622.2 C623.2 C624.2 C627.1 C630.2 C631.2 C632.2 C633.2 C634.2 C635.2 C636.1 C637.1 C638.2 C639.2 C640.2 C641.2 C642.2 C645.2 C646.2 C648.2 C650.1 C651.1 C652.1 C653.1 C654.1 C657.2 C658.2 C660.1 C661.2 C662.2 C663.2 C664.2 C666.2 C667.2 C668.1 C669.1 C670.1 C671.1 C672.1 C673.1 C675.2 C676.2 C677.1 C678.1 C679.1 C680.1 C681.1 C682.2 C683.2 C685.2 C686.2 C687.2 C689.1 C690.2 C692.2 C693.1 C694.1 C695.1 C696.1 C699.2 C700.2 C701.2 C704.2 C706.2 C707.2 C708.2 C709.2 C712.2 C713.2 C714.2 C715.2 C717.2 C718.2 C719.2 C722.1 C723.2 C724.2 C725.2 C726.1 C734.2 C735.2 C736.2 C737.2 C738.2 C740.2 C747.1 C749.1 C750.1 C751.1 C752.1 C753.1 C756.1 C757.1 C758.1 C759.1 C760.1 C764.2 C771.2 C772.2 C775.2 J57.A01(GND) J57.A03(DP1_M2C_N) J57.A04(GND) J57.A05(GND) J57.A07(DP2_M2C_N) J57.A08(GND) J57.A09(GND) J57.A11(DP3_M2C_N) J57.A12(GND) J57.A13(GND) J57.A15(DP4_M2C_N) J57.A16(GND) J57.A17(GND) J57.A19(DP5_M2C_N) J57.A20(GND) J57.A21(GND) J57.A23(DP1_C2M_N) J57.A24(GND) J57.A25(GND) J57.A27(DP2_C2M_N) J57.A28(GND) J57.A29(GND) J57.A31(DP3_C2M_N) J57.A32(GND) J57.A33(GND) J57.A35(DP4_C2M_N) J57.A36(GND) J57.A37(GND) J57.A39(DP5_C2M_N) J57.A40(GND) J57.B02(GND) J57.B03(GND) J57.B05(DP9_M2C_N) J57.B06(GND) J57.B07(GND) J57.B09(DP8_M2C_N) J57.B10(GND) J57.B11(GND) J57.B12(DP7_M2C_P) J57.B13(DP7_M2C_N) J57.B14(GND) J57.B15(GND) J57.B17(DP6_M2C_N) J57.B18(GND) J57.B19(GND) J57.B22(GND) J57.B23(GND) J57.B25(DP9_C2M_N) J57.B26(GND) J57.B27(GND) J57.B29(DP8_C2M_N) J57.B30(GND) J57.B31(GND) J57.B33(DP7_C2M_N) J57.B34(GND) J57.B35(GND) J57.B37(DP6_C2M_N) J57.B38(GND) J57.B39(GND) J57.C01(GND) J57.C03(DP0_C2M_N) J57.C04(GND) J57.C05(GND) J57.C07(DP0_M2C_N) J57.C08(GND) J57.C09(GND) J57.C12(GND) J57.C13(GND) J57.C16(GND) J57.C17(GND) J57.C20(GND) J57.C21(GND) J57.C24(GND) J57.C25(GND) J57.C28(GND) J57.C29(GND) J57.C32(GND) J57.C33(GND) J57.C36(GND) J57.C38(GND) J57.C40(GND) J57.D02(GND) J57.D03(GND) J57.D06(GND) J57.D07(GND) J57.D10(GND) J57.D13(GND) J57.D16(GND) J57.D19(GND) J57.D22(GND) J57.D25(GND) J57.D28(GND) J57.D37(GND) J57.D39(GND) J57.E01(GND) J57.E04(GND) J57.E05(GND) J57.E08(GND) J57.E11(GND) J57.E14(GND) J57.E17(GND) J57.E20(GND) J57.E23(GND) J57.E26(GND) J57.E29(GND) J57.E32(GND) J57.E35(GND) J57.E38(GND) J57.E40(GND) J57.F02(GND) J57.F03(GND) J57.F06(GND) J57.F09(GND) J57.F12(GND) J57.F15(GND) J57.F18(GND) J57.F21(GND) J57.F24(GND) J57.F27(GND) J57.F30(GND) J57.F33(GND) J57.F36(GND) J57.F39(GND) J57.G01(GND) J57.G04(GND) J57.G05(GND) J57.G08(GND) J57.G11(GND) J57.G14(GND) J57.G17(GND) J57.G20(GND) J57.G23(GND) J57.G26(GND) J57.G29(GND) J57.G32(GND) J57.G35(GND) J57.G38(GND) J57.G40(GND) J57.H03(GND) J57.H06(GND) J57.H09(GND) J57.H12(GND) J57.H15(GND) J57.H18(GND) J57.H21(GND) J57.H24(GND) J57.H27(GND) J57.H30(GND) J57.H33(GND) J57.H36(GND) J57.H39(GND) J57.J01(GND) J57.J04(GND) J57.J05(GND) J57.J08(GND) J57.J11(GND) J57.J14(GND) J57.J17(GND) J57.J20(GND) J57.J23(GND) J57.J26(GND) J57.J29(GND) J57.J32(GND) J57.J35(GND) J57.J38(GND) J57.J40(GND) J57.K02(GND) J57.K03(GND) J57.K06(GND) J57.K09(GND) J57.K12(GND) J57.K15(GND) J57.K18(GND) J57.K21(GND) J57.K24(GND) J57.K27(GND) J57.K30(GND) J57.K33(GND) J57.K36(GND) J57.K39(GND) R93.1 R106.1 R555.1 R560.1 R564.1 R578.1 R591.2 R595.2 R597.2 R602.2 R609.1 R610.1 R613.2 R614.2 R616.1 R617.2 R618.1 R619.2 U11.A9(VSS1) U11.B1(VSSQ1) U11.B3(VSS2) U11.B9(VSSQ2) U11.D1(VSSQ3) U11.D8(VSSQ4) U11.E1(VSS3) U11.E2(VSSQ5) U11.E8(VSSQ6) U11.F9(VSSQ7) U11.G1(VSSQ8) U11.G8(VSS4) U11.G9(VSSQ9) U11.J2(VSS5) U11.J8(VSS6) U11.M1(VSS7) U11.M9(VSS8) U11.P1(VSS9) U11.P9(VSS10) U11.T1(VSS11) U11.T9(VSS12) U12.A9(VSS1) U12.B1(VSSQ1) U12.B3(VSS2) U12.B9(VSSQ2) U12.D1(VSSQ3) U12.D8(VSSQ4) U12.E1(VSS3) U12.E2(VSSQ5) U12.E8(VSSQ6) U12.F9(VSSQ7) U12.G1(VSSQ8) U12.G8(VSS4) U12.G9(VSSQ9) U12.J2(VSS5) U12.J8(VSS6) U12.M1(VSS7) U12.M9(VSS8) U12.P1(VSS9) U12.P9(VSS10) U12.T1(VSS11) U12.T9(VSS12) U14.A9(VSS1) U14.B1(VSSQ1) U14.B3(VSS2) U14.B9(VSSQ2) U14.D1(VSSQ3) U14.D8(VSSQ4) U14.E1(VSS3) U14.E2(VSSQ5) U14.E8(VSSQ6) U14.F9(VSSQ7) U14.G1(VSSQ8) U14.G8(VSS4) U14.G9(VSSQ9) U14.J2(VSS5) U14.J8(VSS6) U14.M1(VSS7) U14.M9(VSS8) U14.P1(VSS9) U14.P9(VSS10) U14.T1(VSS11) U14.T9(VSS12) U15.A9(VSS1) U15.B1(VSSQ1) U15.B3(VSS2) U15.B9(VSSQ2) U15.D1(VSSQ3) U15.D8(VSSQ4) U15.E1(VSS3) U15.E2(VSSQ5) U15.E8(VSSQ6) U15.F9(VSSQ7) U15.G1(VSSQ8) U15.G8(VSS4) U15.G9(VSSQ9) U15.J2(VSS5) U15.J8(VSS6) U15.M1(VSS7) U15.M9(VSS8) U15.P1(VSS9) U15.P9(VSS10) U15.T1(VSS11) U15.T9(VSS12) ; also on sheet 8 9 10 11 12 13 14 15 16 17 18 19 20 21 22 23 24 25 26 27 28 30 31 32 33 35 36
P12V: J57.C35(12P0V) J57.C37(12P0V) ; also on sheet 8 9 12 13 14 15 16 24 26 33
DADADD0: J57.A14(DP4_M2C_P) ; also on sheet 11
DADADD1: J57.A18(DP5_M2C_P) ; also on sheet 11
DADADD2: J57.A22(DP1_C2M_P) ; also on sheet 11
DADADD3: J57.A26(DP2_C2M_P) ; also on sheet 11
DADINTZ: J57.B08(DP8_M2C_P) ; also on sheet 11
DADMD0: J57.A06(DP2_M2C_P) ; also on sheet 11
DADMD1: J57.A10(DP3_M2C_P) ; also on sheet 11
DADOEZ: J57.B04(DP9_M2C_P) ; also on sheet 11
DADSEL0: J57.A30(DP3_C2M_P) ; also on sheet 11
DADSEL1: J57.A34(DP4_C2M_P) ; also on sheet 11
DADSTB: J57.A38(DP5_C2M_P) ; also on sheet 11
DDR3_0_A0: R594.1 U12.N3(A0) U15.N3(A0) ; also on sheet 32
DDR3_0_A1: R569.1 U12.P7(A1) U15.P7(A1) ; also on sheet 32
DDR3_0_A2: R601.1 U12.P3(A2) U15.P3(A2) ; also on sheet 32
DDR3_0_A3: R590.1 U12.N2(A3) U15.N2(A3) ; also on sheet 32
DDR3_0_A4: R568.1 U12.P8(A4) U15.P8(A4) ; also on sheet 32
DDR3_0_A5: R599.1 U12.P2(A5) U15.P2(A5) ; also on sheet 32
DDR3_0_A6: R567.1 U12.R8(A6) U15.R8(A6) ; also on sheet 32
DDR3_0_A7: R608.1 U12.R2(A7) U15.R2(A7) ; also on sheet 32
DDR3_0_A8: R566.1 U12.T8(A8) U15.T8(A8) ; also on sheet 32
DDR3_0_A9: R604.1 U12.R3(A9) U15.R3(A9) ; also on sheet 32
DDR3_0_A10: R572.1 U12.L7(A10/AP) U15.L7(A10/AP) ; also on sheet 32
DDR3_0_A11: R565.1 U12.R7(A11) U15.R7(A11) ; also on sheet 32
DDR3_0_A12: R571.1 U12.N7(A12/BC#) U15.N7(A12/BC#) ; also on sheet 32
DDR3_0_A13: R606.1 U12.T3(A13) U15.T3(A13) ; also on sheet 32
DDR3_0_BA0: R584.1 U12.M2(BA0) U15.M2(BA0) ; also on sheet 32
DDR3_0_BA1: R570.1 U12.N8(BA1) U15.N8(BA1) ; also on sheet 32
DDR3_0_BA2: R585.1 U12.M3(BA2) U15.M3(BA2) ; also on sheet 32
DDR3_0_CASZ: R579.1 U12.K3(CAS#) U15.K3(CAS#) ; also on sheet 32
DDR3_0_CKE: R610.2 U12.K9(CKE) U15.K9(CKE) ; also on sheet 32
DDR3_0_CLK_N: R577.1 U12.K7(CK#) U15.K7(CK#) ; also on sheet 32
DDR3_0_CLK_P: R577.2 U12.J7(CK) U15.J7(CK) ; also on sheet 32
DDR3_0_DQ0: U15.E3(DQ0) ; also on sheet 32
DDR3_0_DQ1: U15.F7(DQ1) ; also on sheet 32
DDR3_0_DQ2: U15.F2(DQ2) ; also on sheet 32
DDR3_0_DQ3: U15.F8(DQ3) ; also on sheet 32
DDR3_0_DQ4: U15.H3(DQ4) ; also on sheet 32
DDR3_0_DQ5: U15.H8(DQ5) ; also on sheet 32
DDR3_0_DQ6: U15.G2(DQ6) ; also on sheet 32
DDR3_0_DQ7: U15.H7(DQ7) ; also on sheet 32
DDR3_0_DQ8: U15.D7(DQ8) ; also on sheet 32
DDR3_0_DQ9: U15.C3(DQ9) ; also on sheet 32
DDR3_0_DQ10: U15.C8(DQ10) ; also on sheet 32
DDR3_0_DQ11: U15.C2(DQ11) ; also on sheet 32
DDR3_0_DQ12: U15.A7(DQ12) ; also on sheet 32
DDR3_0_DQ13: U15.A2(DQ13) ; also on sheet 32
DDR3_0_DQ14: U15.B8(DQ14) ; also on sheet 32
DDR3_0_DQ15: U15.A3(DQ15) ; also on sheet 32
DDR3_0_DQ16: U12.E3(DQ0) ; also on sheet 32
DDR3_0_DQ17: U12.F7(DQ1) ; also on sheet 32
DDR3_0_DQ18: U12.F2(DQ2) ; also on sheet 32
DDR3_0_DQ19: U12.F8(DQ3) ; also on sheet 32
DDR3_0_DQ20: U12.H3(DQ4) ; also on sheet 32
DDR3_0_DQ21: U12.H8(DQ5) ; also on sheet 32
DDR3_0_DQ22: U12.G2(DQ6) ; also on sheet 32
DDR3_0_DQ23: U12.H7(DQ7) ; also on sheet 32
DDR3_0_DQ24: U12.D7(DQ8) ; also on sheet 32
DDR3_0_DQ25: U12.C3(DQ9) ; also on sheet 32
DDR3_0_DQ26: U12.C8(DQ10) ; also on sheet 32
DDR3_0_DQ27: U12.C2(DQ11) ; also on sheet 32
DDR3_0_DQ28: U12.A7(DQ12) ; also on sheet 32
DDR3_0_DQ29: U12.A2(DQ13) ; also on sheet 32
DDR3_0_DQ30: U12.B8(DQ14) ; also on sheet 32
DDR3_0_DQ31: U12.A3(DQ15) ; also on sheet 32
DDR3_0_LDQS0_N: U15.G3(LDQS#) ; also on sheet 32
DDR3_0_LDQS0_P: U15.F3(LDQS) ; also on sheet 32
DDR3_0_LDQS1_N: U12.G3(LDQS#) ; also on sheet 32
DDR3_0_LDQS1_P: U12.F3(LDQS) ; also on sheet 32
DDR3_0_NCS: R607.1 U12.L2(CS#) U15.L2(CS#) ; also on sheet 32
DDR3_0_ODT: R575.1 U12.K1(ODT) U15.K1(ODT) ; also on sheet 32
DDR3_0_RASZ: R561.1 U12.J3(RAS#) U15.J3(RAS#) ; also on sheet 32
DDR3_0_RESETZ: R609.2 U12.T2(RESET#) U15.T2(RESET#) ; also on sheet 32
DDR3_0_UDQS0_N: U15.B7(UDQS#) ; also on sheet 32
DDR3_0_UDQS0_P: U15.C7(UDQS) ; also on sheet 32
DDR3_0_UDQS1_N: U12.B7(UDQS#) ; also on sheet 32
DDR3_0_UDQS1_P: U12.C7(UDQS) ; also on sheet 32
DDR3_0_WEZ: R582.1 U12.L3(WE#) U15.L3(WE#) ; also on sheet 32
DDR3_1_A0: R550.1 U11.N3(A0) U14.N3(A0) ; also on sheet 32
DDR3_1_A1: R587.1 U11.P7(A1) U14.P7(A1) ; also on sheet 32
DDR3_1_A2: R553.1 U11.P3(A2) U14.P3(A2) ; also on sheet 32
DDR3_1_A3: R551.1 U11.N2(A3) U14.N2(A3) ; also on sheet 32
DDR3_1_A4: R600.1 U11.P8(A4) U14.P8(A4) ; also on sheet 32
DDR3_1_A5: R552.1 U11.P2(A5) U14.P2(A5) ; also on sheet 32
DDR3_1_A6: R603.1 U11.R8(A6) U14.R8(A6) ; also on sheet 32
DDR3_1_A7: R554.1 U11.R2(A7) U14.R2(A7) ; also on sheet 32
DDR3_1_A8: R605.1 U11.T8(A8) U14.T8(A8) ; also on sheet 32
DDR3_1_A9: R557.1 U11.R3(A9) U14.R3(A9) ; also on sheet 32
DDR3_1_A10: R573.1 U11.L7(A10/AP) U14.L7(A10/AP) ; also on sheet 32
DDR3_1_A11: R596.1 U11.R7(A11) U14.R7(A11) ; also on sheet 32
DDR3_1_A12: R581.1 U11.N7(A12/BC#) U14.N7(A12/BC#) ; also on sheet 32
DDR3_1_A13: R556.1 U11.T3(A13) U14.T3(A13) ; also on sheet 32
DDR3_1_BA0: R549.1 U11.M2(BA0) U14.M2(BA0) ; also on sheet 32
DDR3_1_BA1: R592.1 U11.N8(BA1) U14.N8(BA1) ; also on sheet 32
DDR3_1_BA2: R548.1 U11.M3(BA2) U14.M3(BA2) ; also on sheet 32
DDR3_1_CASZ: R545.1 U11.K3(CAS#) U14.K3(CAS#) ; also on sheet 32
DDR3_1_CKE: R560.2 U11.K9(CKE) U14.K9(CKE) ; also on sheet 32
DDR3_1_CLK_N: R558.1 U11.K7(CK#) U14.K7(CK#) ; also on sheet 32
DDR3_1_CLK_P: R558.2 U11.J7(CK) U14.J7(CK) ; also on sheet 32
DDR3_1_DQ0: U14.E3(DQ0) ; also on sheet 32
DDR3_1_DQ1: U14.F7(DQ1) ; also on sheet 32
DDR3_1_DQ2: U14.F2(DQ2) ; also on sheet 32
DDR3_1_DQ3: U14.F8(DQ3) ; also on sheet 32
DDR3_1_DQ4: U14.H3(DQ4) ; also on sheet 32
DDR3_1_DQ5: U14.H8(DQ5) ; also on sheet 32
DDR3_1_DQ6: U14.G2(DQ6) ; also on sheet 32
DDR3_1_DQ7: U14.H7(DQ7) ; also on sheet 32
DDR3_1_DQ8: U14.D7(DQ8) ; also on sheet 32
DDR3_1_DQ9: U14.C3(DQ9) ; also on sheet 32
DDR3_1_DQ10: U14.C8(DQ10) ; also on sheet 32
DDR3_1_DQ11: U14.C2(DQ11) ; also on sheet 32
DDR3_1_DQ12: U14.A7(DQ12) ; also on sheet 32
DDR3_1_DQ13: U14.A2(DQ13) ; also on sheet 32
DDR3_1_DQ14: U14.B8(DQ14) ; also on sheet 32
DDR3_1_DQ15: U14.A3(DQ15) ; also on sheet 32
DDR3_1_DQ16: U11.E3(DQ0) ; also on sheet 32
DDR3_1_DQ17: U11.F7(DQ1) ; also on sheet 32
DDR3_1_DQ18: U11.F2(DQ2) ; also on sheet 32
DDR3_1_DQ19: U11.F8(DQ3) ; also on sheet 32
DDR3_1_DQ20: U11.H3(DQ4) ; also on sheet 32
DDR3_1_DQ21: U11.H8(DQ5) ; also on sheet 32
DDR3_1_DQ22: U11.G2(DQ6) ; also on sheet 32
DDR3_1_DQ23: U11.H7(DQ7) ; also on sheet 32
DDR3_1_DQ24: U11.D7(DQ8) ; also on sheet 32
DDR3_1_DQ25: U11.C3(DQ9) ; also on sheet 32
DDR3_1_DQ26: U11.C8(DQ10) ; also on sheet 32
DDR3_1_DQ27: U11.C2(DQ11) ; also on sheet 32
DDR3_1_DQ28: U11.A7(DQ12) ; also on sheet 32
DDR3_1_DQ29: U11.A2(DQ13) ; also on sheet 32
DDR3_1_DQ30: U11.B8(DQ14) ; also on sheet 32
DDR3_1_DQ31: U11.A3(DQ15) ; also on sheet 32
DDR3_1_LDQS0_N: U14.G3(LDQS#) ; also on sheet 32
DDR3_1_LDQS0_P: U14.F3(LDQS) ; also on sheet 32
DDR3_1_LDQS1_N: U11.G3(LDQS#) ; also on sheet 32
DDR3_1_LDQS1_P: U11.F3(LDQS) ; also on sheet 32
DDR3_1_NCS: R589.1 U11.L2(CS#) U14.L2(CS#) ; also on sheet 32
DDR3_1_ODT: R546.1 U11.K1(ODT) U14.K1(ODT) ; also on sheet 32
DDR3_1_RASZ: R544.1 U11.J3(RAS#) U14.J3(RAS#) ; also on sheet 32
DDR3_1_RESETZ: R555.2 U11.T2(RESET#) U14.T2(RESET#) ; also on sheet 32
DDR3_1_UDQS0_N: U14.B7(UDQS#) ; also on sheet 32
DDR3_1_UDQS0_P: U14.C7(UDQS) ; also on sheet 32
DDR3_1_UDQS1_N: U11.B7(UDQS#) ; also on sheet 32
DDR3_1_UDQS1_P: U11.C7(UDQS) ; also on sheet 32
DDR3_1_WEZ: R547.1 U11.L3(WE#) U14.L3(WE#) ; also on sheet 32
DDR_VREF: C568.2 C613.2 C650.2 C670.2 C671.2 C681.2 C689.2 C722.2 C726.2 C747.2 C753.2 C758.2 U11.H1(VREFDQ) U11.M8(VREFCA) U12.H1(VREFDQ) U12.M8(VREFCA) U14.H1(VREFDQ) U14.M8(VREFCA) U15.H1(VREFDQ) U15.M8(VREFCA) ; also on sheet 9 32
DDR_VTT: C536.2 C537.2 C538.2 C539.2 C540.2 C541.2 C542.2 C550.2 C551.2 C552.2 C553.2 C554.2 C555.2 C563.2 C573.2 C580.2 C595.2 C603.2 C606.2 C620.2 C627.2 C636.2 C637.2 C660.2 R544.2 R545.2 R546.2 R547.2 R548.2 R549.2 R550.2 R551.2 R552.2 R553.2 R554.2 R556.2 R557.2 R561.2 R565.2 R566.2 R567.2 R568.2 R569.2 R570.2 R571.2 R572.2 R573.2 R575.2 R579.2 R581.2 R582.2 R584.2 R585.2 R587.2 R590.2 R592.2 R594.2 R596.2 R599.2 R600.2 R601.2 R603.2 R604.2 R605.2 R606.2 R608.2 ; also on sheet 9
DMDP3P3VA: J57.C39(3P3V) ; also on sheet 11
DMDP3P3VB: J57.D38(3P3V) ; also on sheet 11
DMDSPARE0: J57.B16(DP6_M2C_P) ; also on sheet 11
EXT_ARSTZ: J57.A02(DP1_M2C_P) ; also on sheet 12 16 33
M_DCLKA_N: J57.K05(CLK2_M2C_N) ; also on sheet 11
M_DCLKA_P: J57.K04(CLK2_M2C_P) ; also on sheet 11
M_DCLKB_N: J57.J03(CLK3_M2C_N) ; also on sheet 11
M_DCLKB_P: J57.J02(CLK3_M2C_P) ; also on sheet 11
M_DDA00_N: J57.D21(LA17_N_CC) ; also on sheet 11
M_DDA00_P: J57.D20(LA17_P_CC) ; also on sheet 11
M_DDA01_N: J57.C23(LA18_N_CC) ; also on sheet 11
M_DDA01_P: J57.C22(LA18_P_CC) ; also on sheet 11
M_DDA02_N: J57.H23(LA19_N) ; also on sheet 11
M_DDA02_P: J57.H22(LA19_P) ; also on sheet 11
M_DDA03_N: J57.G22(LA20_N) ; also on sheet 11
M_DDA03_P: J57.G21(LA20_P) ; also on sheet 11
M_DDA04_N: J57.H26(LA21_N) ; also on sheet 11
M_DDA04_P: J57.H25(LA21_P) ; also on sheet 11
M_DDA05_N: J57.G25(LA22_N) ; also on sheet 11
M_DDA05_P: J57.G24(LA22_P) ; also on sheet 11
M_DDA06_N: J57.D24(LA23_N) ; also on sheet 11
M_DDA06_P: J57.D23(LA23_P) ; also on sheet 11
M_DDA07_N: J57.H29(LA24_N) ; also on sheet 11
M_DDA07_P: J57.H28(LA24_P) ; also on sheet 11
M_DDA08_N: J57.G28(LA25_N) ; also on sheet 11
M_DDA08_P: J57.G27(LA25_P) ; also on sheet 11
M_DDA09_N: J57.D27(LA26_N) ; also on sheet 11
M_DDA09_P: J57.D26(LA26_P) ; also on sheet 11
M_DDA10_N: J57.C27(LA27_N) ; also on sheet 11
M_DDA10_P: J57.C26(LA27_P) ; also on sheet 11
M_DDA11_N: J57.H32(LA28_N) ; also on sheet 11
M_DDA11_P: J57.H31(LA28_P) ; also on sheet 11
M_DDA12_N: J57.G31(LA29_N) ; also on sheet 11
M_DDA12_P: J57.G30(LA29_P) ; also on sheet 11
M_DDA13_N: J57.H35(LA30_N) ; also on sheet 11
M_DDA13_P: J57.H34(LA30_P) ; also on sheet 11
M_DDA14_N: J57.G34(LA31_N) ; also on sheet 11
M_DDA14_P: J57.G33(LA31_P) ; also on sheet 11
M_DDA15_N: J57.H38(LA32_N) ; also on sheet 11
M_DDA15_P: J57.H37(LA32_P) ; also on sheet 11
M_DDB00_N: J57.K26(HB00_CC_N) ; also on sheet 11
M_DDB00_P: J57.K25(HB00_CC_P) ; also on sheet 11
M_DDB01_N: J57.J25(HB01_N) ; also on sheet 11
M_DDB01_P: J57.J24(HB01_P) ; also on sheet 11
M_DDB02_N: J57.F23(HB02_N) ; also on sheet 11
M_DDB02_P: J57.F22(HB02_P) ; also on sheet 11
M_DDB03_N: J57.E22(HB03_N) ; also on sheet 11
M_DDB03_P: J57.E21(HB03_P) ; also on sheet 11
M_DDB04_N: J57.F26(HB04_N) ; also on sheet 11
M_DDB04_P: J57.F25(HB04_P) ; also on sheet 11
M_DDB05_N: J57.E25(HB05_N) ; also on sheet 11
M_DDB05_P: J57.E24(HB05_P) ; also on sheet 11
M_DDB06_N: J57.K29(HB06_N_CC) ; also on sheet 11
M_DDB06_P: J57.K28(HB06_P_CC) ; also on sheet 11
M_DDB07_N: J57.J28(HB07_N) ; also on sheet 11
M_DDB07_P: J57.J27(HB07_P) ; also on sheet 11
M_DDB08_N: J57.F29(HB08_N) ; also on sheet 11
M_DDB08_P: J57.F28(HB08_P) ; also on sheet 11
M_DDB09_N: J57.E28(HB09_N) ; also on sheet 11
M_DDB09_P: J57.E27(HB09_P) ; also on sheet 11
M_DDB10_N: J57.K32(HB10_N) ; also on sheet 11
M_DDB10_P: J57.K31(HB10_P) ; also on sheet 11
M_DDB11_N: J57.J31(HB11_N) ; also on sheet 11
M_DDB11_P: J57.J30(HB11_P) ; also on sheet 11
M_DDB12_N: J57.F32(HB12_N) ; also on sheet 11
M_DDB12_P: J57.F31(HB12_P) ; also on sheet 11
M_DDB13_N: J57.E31(HB13_N) ; also on sheet 11
M_DDB13_P: J57.E30(HB13_P) ; also on sheet 11
M_DDB14_N: J57.K35(HB14_N) ; also on sheet 11
M_DDB14_P: J57.K34(HB14_P) ; also on sheet 11
M_DDB15_N: J57.J34(HB15_N) ; also on sheet 11
M_DDB15_P: J57.J33(HB15_P) ; also on sheet 11
M_SCTRLA_N: J57.G37(LA33_N) ; also on sheet 11
M_SCTRLA_P: J57.G36(LA33_P) ; also on sheet 11
M_SCTRLB_N: J57.F35(HB16_N) ; also on sheet 11
M_SCTRLB_P: J57.F34(HB16_P) ; also on sheet 11
P1P1V: C23.1 C49.1 C527.1 C530.1 C616.1 C617.1 C623.1 C624.1 C630.1 C631.1 C634.1 C635.1 C640.1 C641.1 C645.1 C646.1 C657.1 C658.1 C662.1 C663.1 C666.1 C667.1 C675.1 C676.1 C682.1 C683.1 C685.1 C686.1 C699.1 C700.1 C701.1 C704.1 C707.1 C708.1 C709.1 C713.1 C714.1 C718.1 C719.1 C723.1 C724.1 C736.1 U13.M10(VCC) U13.M14(VCC) U13.M20(VCC) U13.N11(VCC) U13.N13(VCC) U13.N15(VCC) U13.N17(VCC) U13.N19(VCC) U13.N21(VCC) U13.P10(VCC) U13.P12(VCC) U13.P14(VCC) U13.P16(VCC) U13.P18(VCC) U13.P20(VCC) U13.R11(VCC) U13.R13(VCC) U13.R15(VCC) U13.R17(VCC) U13.R19(VCC) U13.R21(VCC) U13.T10(VCC) U13.T12(VCC) U13.T14(VCC) U13.T16(VCC) U13.T18(VCC) U13.T20(VCC) U13.U11(VCC) U13.U13(VCC) U13.U15(VCC) U13.U17(VCC) U13.U19(VCC) U13.U21(VCC) U13.V10(VCC) U13.V12(VCC) U13.V14(VCC) U13.V16(VCC) U13.V18(VCC) U13.V20(VCC) ; also on sheet 8
P1P1V_FIL: C46.1 C544.1 C612.1 C618.1 C622.1 C632.1 C633.1 C648.1 C692.1 C706.1 C712.1 C725.1 C737.1 U13.L9(VCCP) U13.L11(VCCP) U13.L15(VCCP) U13.L19(VCCP) U13.L20(VCCP) U13.W11(VCCP) U13.W13(VCCP) U13.W17(VCCP) U13.W19(VCCP) U13.W21(VCCP) ; also on sheet 8
P1P5V: C52.2 C53.2 C54.2 C55.2 C60.2 C61.2 C62.2 C63.2 C566.2 C567.2 C579.2 C581.2 C582.2 C583.2 C585.2 C621.2 C651.2 C652.2 C653.2 C654.2 C668.2 C669.2 C672.2 C673.2 C677.2 C678.2 C679.2 C680.2 C693.2 C694.2 C695.2 C696.2 C749.2 C750.2 C751.2 C752.2 C756.2 C757.2 C759.2 C760.2 R589.2 R607.2 U11.A1(VDDQ1) U11.A8(VDDQ2) U11.B2(VDD1) U11.C1(VDDQ3) U11.C9(VDDQ4) U11.D2(VDDQ5) U11.D9(VDD2) U11.E9(VDDQ6) U11.F1(VDDQ7) U11.G7(VDD3) U11.H2(VDDQ8) U11.H9(VDDQ9) U11.K2(VDD4) U11.K8(VDD5) U11.N1(VDD6) U11.N9(VDD7) U11.R1(VDD8) U11.R9(VDD9) U12.A1(VDDQ1) U12.A8(VDDQ2) U12.B2(VDD1) U12.C1(VDDQ3) U12.C9(VDDQ4) U12.D2(VDDQ5) U12.D9(VDD2) U12.E9(VDDQ6) U12.F1(VDDQ7) U12.G7(VDD3) U12.H2(VDDQ8) U12.H9(VDDQ9) U12.K2(VDD4) U12.K8(VDD5) U12.N1(VDD6) U12.N9(VDD7) U12.R1(VDD8) U12.R9(VDD9) U14.A1(VDDQ1) U14.A8(VDDQ2) U14.B2(VDD1) U14.C1(VDDQ3) U14.C9(VDDQ4) U14.D2(VDDQ5) U14.D9(VDD2) U14.E9(VDDQ6) U14.F1(VDDQ7) U14.G7(VDD3) U14.H2(VDDQ8) U14.H9(VDDQ9) U14.K2(VDD4) U14.K8(VDD5) U14.N1(VDD6) U14.N9(VDD7) U14.R1(VDD8) U14.R9(VDD9) U15.A1(VDDQ1) U15.A8(VDDQ2) U15.B2(VDD1) U15.C1(VDDQ3) U15.C9(VDDQ4) U15.D2(VDDQ5) U15.D9(VDD2) U15.E9(VDDQ6) U15.F1(VDDQ7) U15.G7(VDD3) U15.H2(VDDQ8) U15.H9(VDDQ9) U15.K2(VDD4) U15.K8(VDD5) U15.N1(VDD6) U15.N9(VDD7) U15.R1(VDD8) U15.R9(VDD9) ; also on sheet 8 9 25 32 33
P1P5V_FIL: C45.1 C578.1 C591.1 C601.1 C604.1 C607.1 C687.1 C738.1 U13.M8(VCCD_FPLL) U13.M15(VCCD_FPLL) U13.N22(VCCD_FPLL) U13.V9(VCCD_FPLL) U13.V22(VCCD_FPLL) U13.W15(VCCD_FPLL) ; also on sheet 9 30
P2P5V: C638.1 C690.1 C740.1 C771.1 C772.1 U13.AA9(VCCPD5) U13.AE4(VCCIO5A) U13.F1(VCCIO6A) U13.K9(VCCPD6) U13.K26(VCCBAT) ; also on sheet 9 32 33
P2P5V_FIL: C47.1 C590.1 C592.1 C608.1 C639.1 C642.1 C661.1 C664.1 C715.1 C717.1 C734.1 C735.1 C775.1 U13.M12(VCC_AUX) U13.M16(VCCA_FPLL) U13.M18(VCC_AUX) U13.P9(VCCA_FPLL) U13.P22(VCCA_FPLL) U13.T9(VCCA_FPLL) U13.T22(VCCA_FPLL) U13.W12(VCC_AUX) U13.W16(VCCA_FPLL) U13.W18(VCC_AUX) ; also on sheet 9 30
P3P3V: C71.1 C615.1 C764.1 U13.AA24(VCCPGM) U13.K5(VCCPGM) ; also on sheet 9 25 30 31 33
S_DCLKA_N: J57.H05(CLK0_M2C_N) ; also on sheet 36
S_DCLKA_P: J57.H04(CLK0_M2C_P) ; also on sheet 36
S_DCLKB_N: J57.G03(CLK1_M2C_N) ; also on sheet 36
S_DCLKB_P: J57.G02(CLK1_M2C_P) ; also on sheet 36
S_DDA00_N: J57.G07(LA00_N_CC) ; also on sheet 36
S_DDA00_P: J57.G06(LA00_P_CC) ; also on sheet 36
S_DDA01_N: J57.D09(LA01_N_CC) ; also on sheet 36
S_DDA01_P: J57.D08(LA01_P_CC) ; also on sheet 36
S_DDA02_N: J57.H08(LA02_N) ; also on sheet 36
S_DDA02_P: J57.H07(LA02_P) ; also on sheet 36
S_DDA03_N: J57.G10(LA03_N) ; also on sheet 36
S_DDA03_P: J57.G09(LA03_P) ; also on sheet 36
S_DDA04_N: J57.H11(LA04_N) ; also on sheet 36
S_DDA04_P: J57.H10(LA04_P) ; also on sheet 36
S_DDA05_N: J57.D12(LA05_N) ; also on sheet 36
S_DDA05_P: J57.D11(LA05_P) ; also on sheet 36
S_DDA06_N: J57.C11(LA06_N) ; also on sheet 36
S_DDA06_P: J57.C10(LA06_P) ; also on sheet 36
S_DDA07_N: J57.H14(LA07_N) ; also on sheet 36
S_DDA07_P: J57.H13(LA07_P) ; also on sheet 36
S_DDA08_N: J57.G13(LA08_N) ; also on sheet 36
S_DDA08_P: J57.G12(LA08_P) ; also on sheet 36
S_DDA09_N: J57.D15(LA09_N) ; also on sheet 36
S_DDA09_P: J57.D14(LA09_P) ; also on sheet 36
S_DDA10_N: J57.C15(LA10_N) ; also on sheet 36
S_DDA10_P: J57.C14(LA10_P) ; also on sheet 36
S_DDA11_N: J57.H17(LA11_N) ; also on sheet 36
S_DDA11_P: J57.H16(LA11_P) ; also on sheet 36
S_DDA12_N: J57.G16(LA12_N) ; also on sheet 36
S_DDA12_P: J57.G15(LA12_P) ; also on sheet 36
S_DDA13_N: J57.D18(LA13_N) ; also on sheet 36
S_DDA13_P: J57.D17(LA13_P) ; also on sheet 36
S_DDA14_N: J57.C19(LA14_N) ; also on sheet 36
S_DDA14_P: J57.C18(LA14_P) ; also on sheet 36
S_DDA15_N: J57.H20(LA15_N) ; also on sheet 36
S_DDA15_P: J57.H19(LA15_P) ; also on sheet 36
S_DDB00_N: J57.F05(HA00_N_CC) ; also on sheet 36
S_DDB00_P: J57.F04(HA00_P_CC) ; also on sheet 36
S_DDB01_N: J57.E03(HA01_N_CC) ; also on sheet 36
S_DDB01_P: J57.E02(HA01_P_CC) ; also on sheet 36
S_DDB02_N: J57.K08(HA02_N) ; also on sheet 36
S_DDB02_P: J57.K07(HA02_P) ; also on sheet 36
S_DDB03_N: J57.J07(HA03_N) ; also on sheet 36
S_DDB03_P: J57.J06(HA03_P) ; also on sheet 36
S_DDB04_N: J57.F08(HA04_N) ; also on sheet 36
S_DDB04_P: J57.F07(HA04_P) ; also on sheet 36
S_DDB05_N: J57.E07(HA05_N) ; also on sheet 36
S_DDB05_P: J57.E06(HA05_P) ; also on sheet 36
S_DDB06_N: J57.K11(HA06_N) ; also on sheet 36
S_DDB06_P: J57.K10(HA06_P) ; also on sheet 36
S_DDB07_N: J57.J10(HA07_N) ; also on sheet 36
S_DDB07_P: J57.J09(HA07_P) ; also on sheet 36
S_DDB08_N: J57.F11(HA08_N) ; also on sheet 36
S_DDB08_P: J57.F10(HA08_P) ; also on sheet 36
S_DDB09_N: J57.E10(HA09_N) ; also on sheet 36
S_DDB09_P: J57.E09(HA09_P) ; also on sheet 36
S_DDB10_N: J57.K14(HA10_N) ; also on sheet 36
S_DDB10_P: J57.K13(HA10_P) ; also on sheet 36
S_DDB11_N: J57.J13(HA11_N) ; also on sheet 36
S_DDB11_P: J57.J12(HA11_P) ; also on sheet 36
S_DDB12_N: J57.F14(HA12_N) ; also on sheet 36
S_DDB12_P: J57.F13(HA12_P) ; also on sheet 36
S_DDB13_N: J57.E13(HA13_N) ; also on sheet 36
S_DDB13_P: J57.E12(HA13_P) ; also on sheet 36
S_DDB14_N: J57.J16(HA14_N) ; also on sheet 36
S_DDB14_P: J57.J15(HA14_P) ; also on sheet 36
S_DDB15_N: J57.F17(HA15_N) ; also on sheet 36
S_DDB15_P: J57.F16(HA15_P) ; also on sheet 36
S_DMDP3P3VA: J57.D36(3P3V) ; also on sheet 36
S_DMDP3P3VB: J57.D40(3P3V) ; also on sheet 36
S_SCTRLA_N: J57.G19(LA16_N) ; also on sheet 36
S_SCTRLA_P: J57.G18(LA16_P) ; also on sheet 36
S_SCTRLB_N: J57.E16(HA16_N) ; also on sheet 36
S_SCTRLB_P: J57.E15(HA16_P) ; also on sheet 36
SSP0_CLK_DMD: J57.B32(DP7_C2M_P) ; also on sheet 20
SSP0_CSZ0_DAD1: J57.B24(DP9_C2M_P) ; also on sheet 20
SSP0_CSZ1_DMD: J57.C06(DP0_M2C_P) ; also on sheet 20
SSP0_CSZ5_DAD2: J57.B28(DP8_C2M_P) ; also on sheet 17
SSP0_RXD: J57.B36(DP6_C2M_P) ; also on sheet 11 12 20 25
SSP0_TXD_DMD: J57.C02(DP0_C2M_P) ; also on sheet 20
N18522675: R616.2 U14.L8(ZQ)
N18527288: R578.2 U11.L8(ZQ)
N18536772: R564.2 U12.L8(ZQ)
N18538448: R618.2 U15.L8(ZQ)
N18693988: R106.2 U13.AF1(RREF_BR)
N18693993: R93.2 U13.F30(RREF_TL)
N18796048: R617.1 U15.E7(LDM)
N18796050: R619.1 U15.D3(UDM)
N19329690: R597.1 U12.E7(LDM)
N19329692: R602.1 U12.D3(UDM)
N19330770: R614.1 U14.E7(LDM)
N19330772: R613.1 U14.D3(UDM)
N19331069: R595.1 U11.E7(LDM)
N19331071: R591.1 U11.D3(UDM)

Not connected (* = marked no-connect by the designer): J57 B01(RES1)* B20(GBTCLK1_M2C_P)* B21(GBTCLK1_M2C_N)* B40(RES0)* C30(SCL)* C31(SDA)* C34(GA0)* D01(PG_C2M)* D04(GBTCLK0_M2C_P)* D05(GBTCLK0_M2C_N)* D29(TCK)* D30(TDI)* D31(TDO)* D32(3P3VAUX)* D33(TMS)* D34(TRST_L)* D35(GA1)* E18(HA20_P)* E19(HA20_N)* E33(HB19_P)* E34(HB19_N)* E36(HB21_P)* E37(HB21_N)* E39(VADJ)* F01(PG_M2C)* F19(HA19_P)* F20(HA19_N)* F37(HB20_P)* F38(HB20_N)* F40(VADJ)* G39(VADJ)* H01(VREF_A_M2C)* H02(PRSNT_M2C_L)* H40(VADJ)* J18(HA18_P)* J19(HA18_N)* J21(HA22_P)* J22(HA22_N)* J36(HB18_P)* J37(HB18_N)* J39(VIO_B_M2C)* K01(VREF_B_M2C)* K16(HA17_P_CC)* K17(HA17_N_CC)* K19(HA21_P)* K20(HA21_N)* K22(HA23_P)* K23(HA23_N)* K37(HB17_P_CC)* K38(HB17_N_CC)* K40(VIO_B_M2C)*; U11 J1(NC1)* J9(NC2)* L1(NC3)* L9(NC4)* M7(NC5)* T7(NC6)*; U12 J1(NC1)* J9(NC2)* L1(NC3)* L9(NC4)* M7(NC5)* T7(NC6)*; U13 A2(NC)* A3(NC)* A7(NC)* A8(NC)* AA1(DNU)* AA3(DNU)* AA4(DNU)* AB8(NC)* AB26(DNU)* AC1(DNU)* AC3(DNU)* AC4(DNU)* AC7(NC)* AC9(NC)* AC10(NC)* AD6(NC)* AD9(NC)* AE5(DNU)* AE8(NC)* AE9(NC)* AF2(DNU)* AF9(NC)* AG2(DNU)* AG3(NC)* AG4(NC)* AG5(NC)* AG7(NC)* AG8(NC)* AH1(NC)* AH2(NC)* AH4(NC)* AH5(NC)* AH7(NC)* AH8(NC)* AJ1(NC)* AJ3(NC)* AJ4(NC)* AJ7(NC)* AJ9(NC)* AK2(NC)* AK3(NC)* AK7(NC)* AK8(NC)* B1(NC)* B3(NC)* B4(NC)* B7(NC)* B9(NC)* C1(NC)* C2(NC)* C4(NC)* C7(NC)* C8(NC)* D1(NC)* D2(NC)* D3(NC)* D4(NC)* D8(NC)* E1(NC)* E3(DNU)* E7(NC)* E29(DNU)* F7(NC)* F8(NC)* F29(DNU)* G3(DNU)* G4(DNU)* G8(NC)* G9(NC)* H5(DNU)* H9(NC)* J1(DNU)* J3(DNU)* J4(DNU)* J7(NC)* J8(NC)* J9(NC)* K4(DNU)* K15(DNU_17)* L1(DNU)* L3(DNU)* L4(DNU)* M4(DNU)* N1(DNU)* N3(DNU)* N4(DNU)* R3(DNU)* R4(DNU)* R7(DNU)* T8(DNU)* U1(DNU)* U3(DNU)* U4(DNU)* U7(DNU)* V8(DNU)* W3(DNU)* W4(DNU)* Y16(DNU)*; U14 J1(NC1)* J9(NC2)* L1(NC3)* L9(NC4)* M7(NC5)* T7(NC6)*; U15 J1(NC1)* J9(NC2)* L1(NC3)* L9(NC4)* M7(NC5)* T7(NC6)*

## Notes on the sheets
sheet 1
- Revision A:
  Initial Release
  Revision B:
  All Pages: Resequenced reference designators to align with layout
  Page 1: Updated notes with correct voltage names
  Updated index
  Page 4: Rearranged DDR3_1_DQ[15:0] for routability
  Revision C:
  Page 3: Change U5 to Do Not Install
  Updated C545 and C549 as Do Not Install
  Changed U506 to 75 Mhz
  Page 11: Added Note Connecting pin 15 of U24 to P3P3V
  Page 8: Changed R89, R90, R91, R92, and R541 to 0 ohms.
  Revision D:
  Page 3: Changed net name TEST_4A_AC6 to VX1_3D_EN.
  Changed net name TEST_4A_AE6 to VX1_LR_SYNC.
  Page 8: Added R190, R191, R192, and R193.
  Changed net name TEST_4A_AC6 to VX1_3D_EN.
  Changed net name TEST_4A_AE6 to VX1_LR_SYNC.
  Page 11: Connected pin 15 of U24 to P3P3V.
  Page 16: Changed C799 and C801 to 1800pF.
  Page 21: Added note to ballast circuit.
  Page 22: Added R188 and R189.
  Page 23: Changed RN501 to Install, added J52 header.
  Page 24: Changed RN500 to Install, added J53 header.
  Revision E:
  Page 11: Changed U24-10, C85 connection from P3P3V to P5V_S.
  Revision F:
  Page 3: Added U514, Y1, R745, R746, R747, C966
  Page 3: Removed FB502, C534, U506
  Page 8: Added J54, J55, and J56
  Page 22: Added R748 and connection to GPIO_34
  Revision G:
  Page 8: Added Off-Page connections to TEST_4A_AF7 and TEST_4B_AD8.
  Page 30: Added TEST_4A_AF7 connection to GPIO_24 on U32
  Revision H:
  Page 3: Updated FE_12V to RE_5V
  Removed nets: "USB+5V", "USB_D+", USB_D-"
  Added I2C nets "SCL1", "SDA1"
  Rearraged nets "VX1_LR_SYNC", "FE_RST", "SDA0",  "I2C_BUSY"
  Page 14: Removed J51
  Page 15: Removed J50
  Page 34: Added J57 FMC Connector
- (C) COPYRIGHT 2023
         Texas Instruments
        All Rights Reserved
sheet 2
- Main Controller Bus B
- Secondary Controller Bus B
- Main Controller Bus A
- Secondary Controller Bus A
- Max Power Transfer (pins):
  1A at 12V
- FMC TO DMD
- (C) COPYRIGHT 2023
         Texas Instruments
        All Rights Reserved
sheet 3
- NOTES, UNLESS OTHERWISE SPECIFIED:
- 1. The netname "P1P1V" represents connection to the +1.1V FPGA power plane
  2. The netname "P1P1V_FIL" represents connection to the +1.1V filtered FPGA power plane
  3. The netname "P1P1V_M" represents connection to the +1.1V Master ASIC power plane
  4. The netname "P1P1V_S" represents connection to the +1.1V Slave ASIC power plane
  5. The netname "P1P15V" represents connection to the +1.15V FPGA power plane
  6. The netname "P1P15V" represents connection to the +1.15V filtered FPGA power plane
  7. The netname "P1P5V" represents connection to the +1.5V FPGA power plane
  8. The netname "P1P5V_FIL" represents connection to the +1.5V filtered FPGA power plane
  9. The netname "P1P8V_M" represents connection to the +1.8V Master ASIC power plane
  10. The netname "P1P8V_S" represents connection to the +1.8V Slave ASIC power plane
  11. The netname "A1P8V_M" represents connection to the +1.8V Master ASIC power plane for the PLLs
  12. The netname "A1P8V_S" represents connection to the +1.8V Slave ASIC power plane for the PLLs
  13. The netname "P2P5V" represents connection to the +2.5V FPGA power plane
  14. The netname "P2P5V_FIL" represents connection to the +2.5V filtered FPGA power plane
  15. The netname "P2P5V_M" represents connection to the +2.5V Master ASIC power plane
  16. The netname "P2P5V_S" represents connection to the +2.5V Slave ASIC power plane
  17. The netname "P3P3V" represents connection to the +3.3V FPGA power plane
  18. The netname "P3P3V_M" represents connection to the +3.3V Master ASIC power plane
  19. The netname "P3P3V_S" represents connection to the +3.3V Slave ASIC power plane
  20. The netname "P5V_M" represents connection to the +5V Master ASIC power plane
  21. The netname "P5V_S" represents connection to the +5V Slave ASIC power plane
  22. The netname "P12V" represents the connection to the +12.0V power plane.
  23. The netname "GND" represents connection to the ground plane
  24. A "Z" suffix on a signal name indicates an active low signal
  25. All components with designators "U*", "Q*", "D*" are electrostactic discharge sensitive.
  26. All components with designators above 500 are mounted on the bottom side of the board.
  27. All resistor values are in ohms.
- INDEX
- Sheet 1: Cover
  Sheet 2: Block Diagram
  Sheet 3: FPGA Front End I/F
  Sheet 4: FPGA DDR3 I/F
  Sheet 5: DDR3 Memory 1&2
  Sheet 6: DDR3 Memory 3&4
  Sheet 7: FPGA Video Out I/F
  Sheet 8: FPGA Programming/Test MUX
  Sheet 9: FPGA Power
  Sheet 10: FPGA Regulators
  Sheet 11: FPGA Regulators
  Sheet 12: FPGA Ground
  Sheet 13: ASIC Video Input I/F
  Sheet 14: Primary DMD Flex I/F
  Sheet 15: Secondary DMD Flex I/F
  Sheet 16: Input Power and PMD1000 I/F
  Sheet 17: Primary DLPA100 Power Supplies
  Sheet 18: Secondary DLPA100 Power Supplies
  Sheet 19: ColorWheel Drive
  Sheet 20: Fans, CW Index, Peripheral Connectors
  Sheet 21: Primary ASIC GPIO, I2C, and Lamp Ballast
  Sheet 22: GPIO Expander, Keypad Interface and IR
  Sheet 23: Primary ASIC TP, ARM JTAG, RESET
  Sheet 24: Secondary ASIC TP, ARM JTAG
  Sheet 25: Primary RS-232. SPI, and USB
  Sheet 26: Primary ASIC Flash I/F
  Sheet 27: Secondary ASIC Flash I/F
  Sheet 28: ASIC SSI I/F
  Sheet 29: SSI Driver I/F
  Sheet 30: Secondary ASIC GPIO & Smooth Picture I/F
  Sheet 31: Smooth Picture Electronics
  Sheet 32: Primary Power and Bypass Caps
  Sheet 33: Secondary Power and Bypass Caps
  Sheet 34: Output FMC Connector
  Sheet 35: Revison History
  Sheet 36: Important Notice
- DLP072
- Cadence Capture V.16.6
sheet 4
- Block Diagram
- (C) COPYRIGHT 2023
         Texas Instruments
        All Rights Reserved
sheet 5
- DDR3 Memory 1&2
- (C) COPYRIGHT 2023
         Texas Instruments
        All Rights Reserved
sheet 6
- DDR3 Memory 3&4
- (C) COPYRIGHT 2023
         Texas Instruments
        All Rights Reserved
sheet 7
- FPGA - Power
- (C) COPYRIGHT 2023
         Texas Instruments
        All Rights Reserved
